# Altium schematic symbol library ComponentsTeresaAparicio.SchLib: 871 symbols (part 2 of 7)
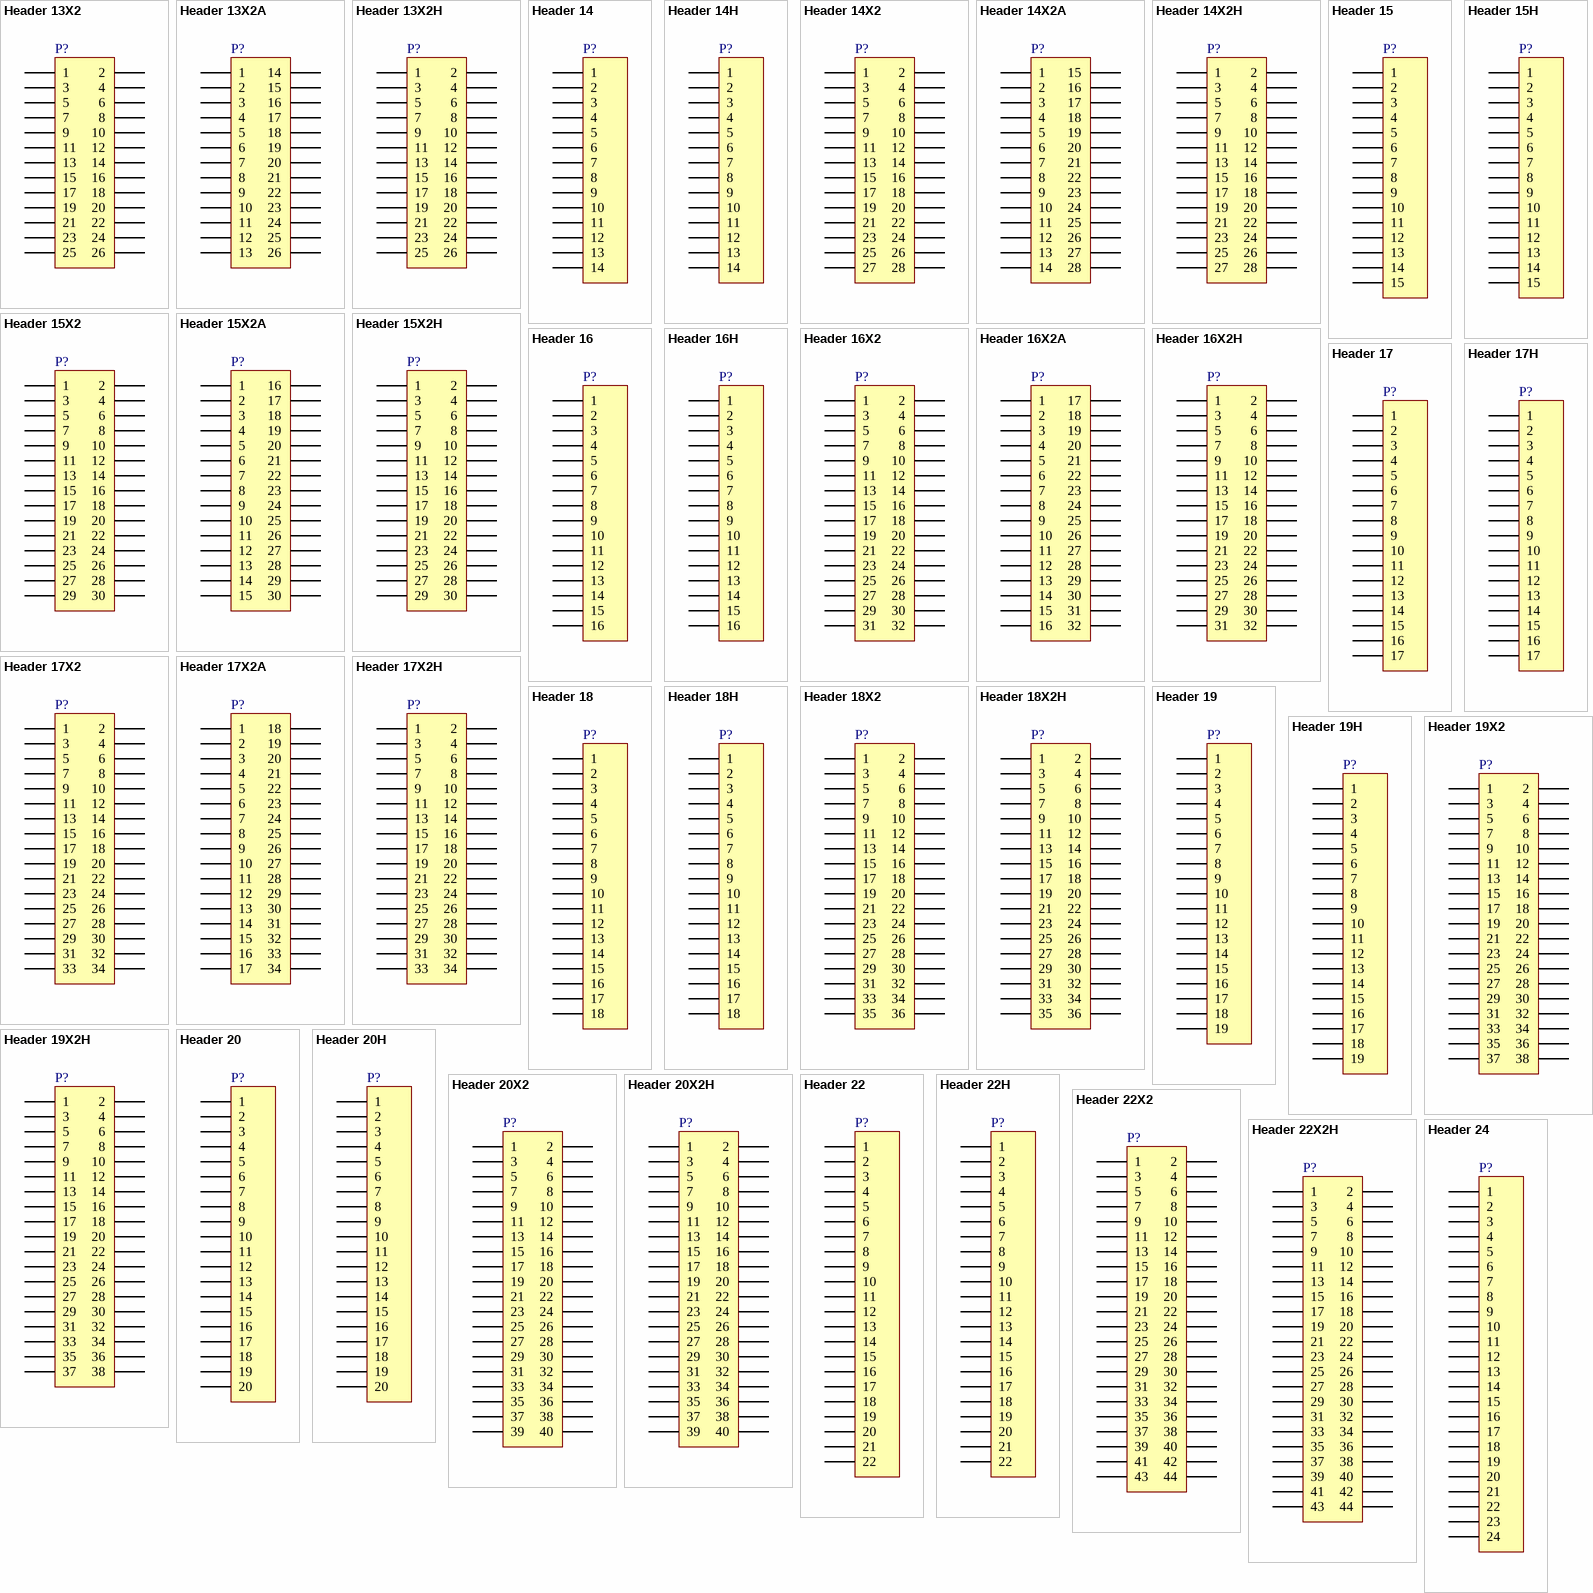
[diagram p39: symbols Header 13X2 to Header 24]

## Header 15X2A
designator P?
Header, 15-Pin, Dual row
footprint HDR2X15_CEN (Connector; Header; 15x2 Position)
signal-integrity model Connector
pins: 1, 2, 3, 4, 5, 6, 7, 8, 9, 10, 11, 12, 13, 14, 15, 16, 17, 18, 19, 20, 21, 22, 23, 24, 25, 26, 27, 28, 29, 30

## Header 15X2H
designator P?
Header, 15-Pin, Dual row, Right Angle
footprint HDR2X15H (Connector; Header; 15x2 Position; Right Angle)
signal-integrity model Connector
pins: 1, 2, 3, 4, 5, 6, 7, 8, 9, 10, 11, 12, 13, 14, 15, 16, 17, 18, 19, 20, 21, 22, 23, 24, 25, 26, 27, 28, 29, 30

## Header 16
designator P?
Header, 16-Pin
footprint HDR1X16 (Connector; Header; 16 Position)
signal-integrity model Connector
pins: 1, 2, 3, 4, 5, 6, 7, 8, 9, 10, 11, 12, 13, 14, 15, 16

## Header 16H
designator P?
Header, 16-Pin, Right Angle
footprint HDR1X16H (Connector; Header; 16 Position; Right Angle)
signal-integrity model Connector
pins: 1, 2, 3, 4, 5, 6, 7, 8, 9, 10, 11, 12, 13, 14, 15, 16

## Header 16X2
designator P?
Header, 16-Pin, Dual row
footprint HDR2X16 (Connector; Header; 16x2 Position)
signal-integrity model Connector
pins: 1, 2, 3, 4, 5, 6, 7, 8, 9, 10, 11, 12, 13, 14, 15, 16, 17, 18, 19, 20, 21, 22, 23, 24, 25, 26, 27, 28, 29, 30, 31, 32

## Header 16X2A
designator P?
Header, 16-Pin, Dual row
footprint HDR2X16_CEN (Connector; Header; 16x2 Position)
signal-integrity model Connector
pins: 1, 2, 3, 4, 5, 6, 7, 8, 9, 10, 11, 12, 13, 14, 15, 16, 17, 18, 19, 20, 21, 22, 23, 24, 25, 26, 27, 28, 29, 30, 31, 32

## Header 16X2H
designator P?
Header, 16-Pin, Dual row, Right Angle
footprint HDR2X16H (Connector; Header; 16x2 Position; Right Angle)
signal-integrity model Connector
pins: 1, 2, 3, 4, 5, 6, 7, 8, 9, 10, 11, 12, 13, 14, 15, 16, 17, 18, 19, 20, 21, 22, 23, 24, 25, 26, 27, 28, 29, 30, 31, 32

## Header 17
designator P?
Header, 17-Pin
footprint HDR1X17 (Connector; Header; 17 Position)
signal-integrity model Connector
pins: 1, 2, 3, 4, 5, 6, 7, 8, 9, 10, 11, 12, 13, 14, 15, 16, 17

## Header 17H
designator P?
Header, 17-Pin, Right Angle
footprint HDR1X17H (Connector; Header; 17 Position; Right Angle)
signal-integrity model Connector
pins: 1, 2, 3, 4, 5, 6, 7, 8, 9, 10, 11, 12, 13, 14, 15, 16, 17

## Header 17X2
designator P?
Header, 17-Pin, Dual row
footprint HDR2X17 (Connector; Header; 17x2 Position)
signal-integrity model Connector
pins: 1, 2, 3, 4, 5, 6, 7, 8, 9, 10, 11, 12, 13, 14, 15, 16, 17, 18, 19, 20, 21, 22, 23, 24, 25, 26, 27, 28, 29, 30, 31, 32, 33, 34

## Header 17X2A
designator P?
Header, 17-Pin, Dual row
footprint HDR2X17_CEN (Connector; Header; 17x2 Position)
signal-integrity model Connector
pins: 1, 2, 3, 4, 5, 6, 7, 8, 9, 10, 11, 12, 13, 14, 15, 16, 17, 18, 19, 20, 21, 22, 23, 24, 25, 26, 27, 28, 29, 30, 31, 32, 33, 34

## Header 17X2H
designator P?
Header, 17-Pin, Dual row, Right Angle
footprint HDR2X17H (Connector; Header; 17x2 Position; Right Angle)
signal-integrity model Connector
pins: 1, 2, 3, 4, 5, 6, 7, 8, 9, 10, 11, 12, 13, 14, 15, 16, 17, 18, 19, 20, 21, 22, 23, 24, 25, 26, 27, 28, 29, 30, 31, 32, 33, 34

## Header 18
designator P?
Header, 18-Pin
footprint HDR1X18 (Connector; Header; 18 Position)
signal-integrity model Connector
pins: 1, 2, 3, 4, 5, 6, 7, 8, 9, 10, 11, 12, 13, 14, 15, 16, 17, 18

## Header 18H
designator P?
Header, 18-Pin, Right Angle
footprint HDR1X18H (Connector; Header; 18 Position; Right Angle)
signal-integrity model Connector
pins: 1, 2, 3, 4, 5, 6, 7, 8, 9, 10, 11, 12, 13, 14, 15, 16, 17, 18

## Header 18X2
designator P?
Header, 18-Pin, Dual row
footprint HDR2X18 (Connector; Header; 18x2 Position)
signal-integrity model Connector
pins: 1, 2, 3, 4, 5, 6, 7, 8, 9, 10, 11, 12, 13, 14, 15, 16, 17, 18, 19, 20, 21, 22, 23, 24, 25, 26, 27, 28, 29, 30, 31, 32, 33, 34, 35, 36

## Header 18X2H
designator P?
Header, 18-Pin, Dual row, Right Angle
footprint HDR2X18H (Connector; Header; 18x2 Position; Right Angle)
signal-integrity model Connector
pins: 1, 2, 3, 4, 5, 6, 7, 8, 9, 10, 11, 12, 13, 14, 15, 16, 17, 18, 19, 20, 21, 22, 23, 24, 25, 26, 27, 28, 29, 30, 31, 32, 33, 34, 35, 36

## Header 19
designator P?
Header, 19-Pin
footprint HDR1X19 (Connector; Header; 19 Position)
signal-integrity model Connector
pins: 1, 2, 3, 4, 5, 6, 7, 8, 9, 10, 11, 12, 13, 14, 15, 16, 17, 18, 19

## Header 19H
designator P?
Header, 19-Pin, Right Angle
footprint HDR1X19H (Connector; Header; 19 Position; Right Angle)
signal-integrity model Connector
pins: 1, 2, 3, 4, 5, 6, 7, 8, 9, 10, 11, 12, 13, 14, 15, 16, 17, 18, 19

## Header 19X2
designator P?
Header, 19-Pin, Dual row
footprint HDR2X19 (Connector; Header; 19x2 Position)
signal-integrity model Connector
pins: 1, 2, 3, 4, 5, 6, 7, 8, 9, 10, 11, 12, 13, 14, 15, 16, 17, 18, 19, 20, 21, 22, 23, 24, 25, 26, 27, 28, 29, 30, 31, 32, 33, 34, 35, 36, 37, 38

## Header 19X2H
designator P?
Header, 19-Pin, Dual row, Right Angle
footprint HDR2X19H (Connector; Header; 19x2 Position; Right Angle)
signal-integrity model Connector
pins: 1, 2, 3, 4, 5, 6, 7, 8, 9, 10, 11, 12, 13, 14, 15, 16, 17, 18, 19, 20, 21, 22, 23, 24, 25, 26, 27, 28, 29, 30, 31, 32, 33, 34, 35, 36, 37, 38

## Header 20
designator P?
Header, 20-Pin
footprint HDR1X20 (Connector; Header; 20 Position)
signal-integrity model Connector
pins: 1, 2, 3, 4, 5, 6, 7, 8, 9, 10, 11, 12, 13, 14, 15, 16, 17, 18, 19, 20

## Header 20H
designator P?
Header, 20-Pin, Right Angle
footprint HDR1X20H (Connector; Header; 20 Position; Right Angle)
signal-integrity model Connector
pins: 1, 2, 3, 4, 5, 6, 7, 8, 9, 10, 11, 12, 13, 14, 15, 16, 17, 18, 19, 20

## Header 20X2
designator P?
Header, 20-Pin, Dual row
footprint HDR2X20 (Connector; Header; 20x2 Position)
signal-integrity model Connector
pins: 1, 2, 3, 4, 5, 6, 7, 8, 9, 10, 11, 12, 13, 14, 15, 16, 17, 18, 19, 20, 21, 22, 23, 24, 25, 26, 27, 28, 29, 30, 31, 32, 33, 34, 35, 36, 37, 38, 39, 40

## Header 20X2H
designator P?
Header, 20-Pin, Dual row, Right Angle
footprint HDR2X20H (Connector; Header; 20x2 Position; Right Angle)
signal-integrity model Connector
pins: 1, 2, 3, 4, 5, 6, 7, 8, 9, 10, 11, 12, 13, 14, 15, 16, 17, 18, 19, 20, 21, 22, 23, 24, 25, 26, 27, 28, 29, 30, 31, 32, 33, 34, 35, 36, 37, 38, 39, 40

## Header 22
designator P?
Header, 22-Pin
footprint HDR1X22 (Connector; Header; 22 Position)
signal-integrity model Connector
pins: 1, 2, 3, 4, 5, 6, 7, 8, 9, 10, 11, 12, 13, 14, 15, 16, 17, 18, 19, 20, 21, 22

## Header 22H
designator P?
Header, 22-Pin, Right Angle
footprint HDR1X22H (Connector; Header; 22 Position; Right Angle)
signal-integrity model Connector
pins: 1, 2, 3, 4, 5, 6, 7, 8, 9, 10, 11, 12, 13, 14, 15, 16, 17, 18, 19, 20, 21, 22

## Header 22X2
designator P?
Header, 22-Pin, Dual row
footprint HDR2X22 (Connector; Header; 22x2 Position)
signal-integrity model Connector
pins: 1, 2, 3, 4, 5, 6, 7, 8, 9, 10, 11, 12, 13, 14, 15, 16, 17, 18, 19, 20, 21, 22, 23, 24, 25, 26, 27, 28, 29, 30, 31, 32, 33, 34, 35, 36, 37, 38, 39, 40, 41, 42, 43, 44

## Header 22X2H
designator P?
Header, 22-Pin, Dual row, Right Angle
footprint HDR2X22H (Connector; Header; 22x2 Position; Right Angle)
signal-integrity model Connector
pins: 1, 2, 3, 4, 5, 6, 7, 8, 9, 10, 11, 12, 13, 14, 15, 16, 17, 18, 19, 20, 21, 22, 23, 24, 25, 26, 27, 28, 29, 30, 31, 32, 33, 34, 35, 36, 37, 38, 39, 40, 41, 42, 43, 44

## Header 24
designator P?
Header, 24-Pin
footprint HDR1X24 (Connector; Header; 24 Position)
signal-integrity model Connector
pins: 1, 2, 3, 4, 5, 6, 7, 8, 9, 10, 11, 12, 13, 14, 15, 16, 17, 18, 19, 20, 21, 22, 23, 24

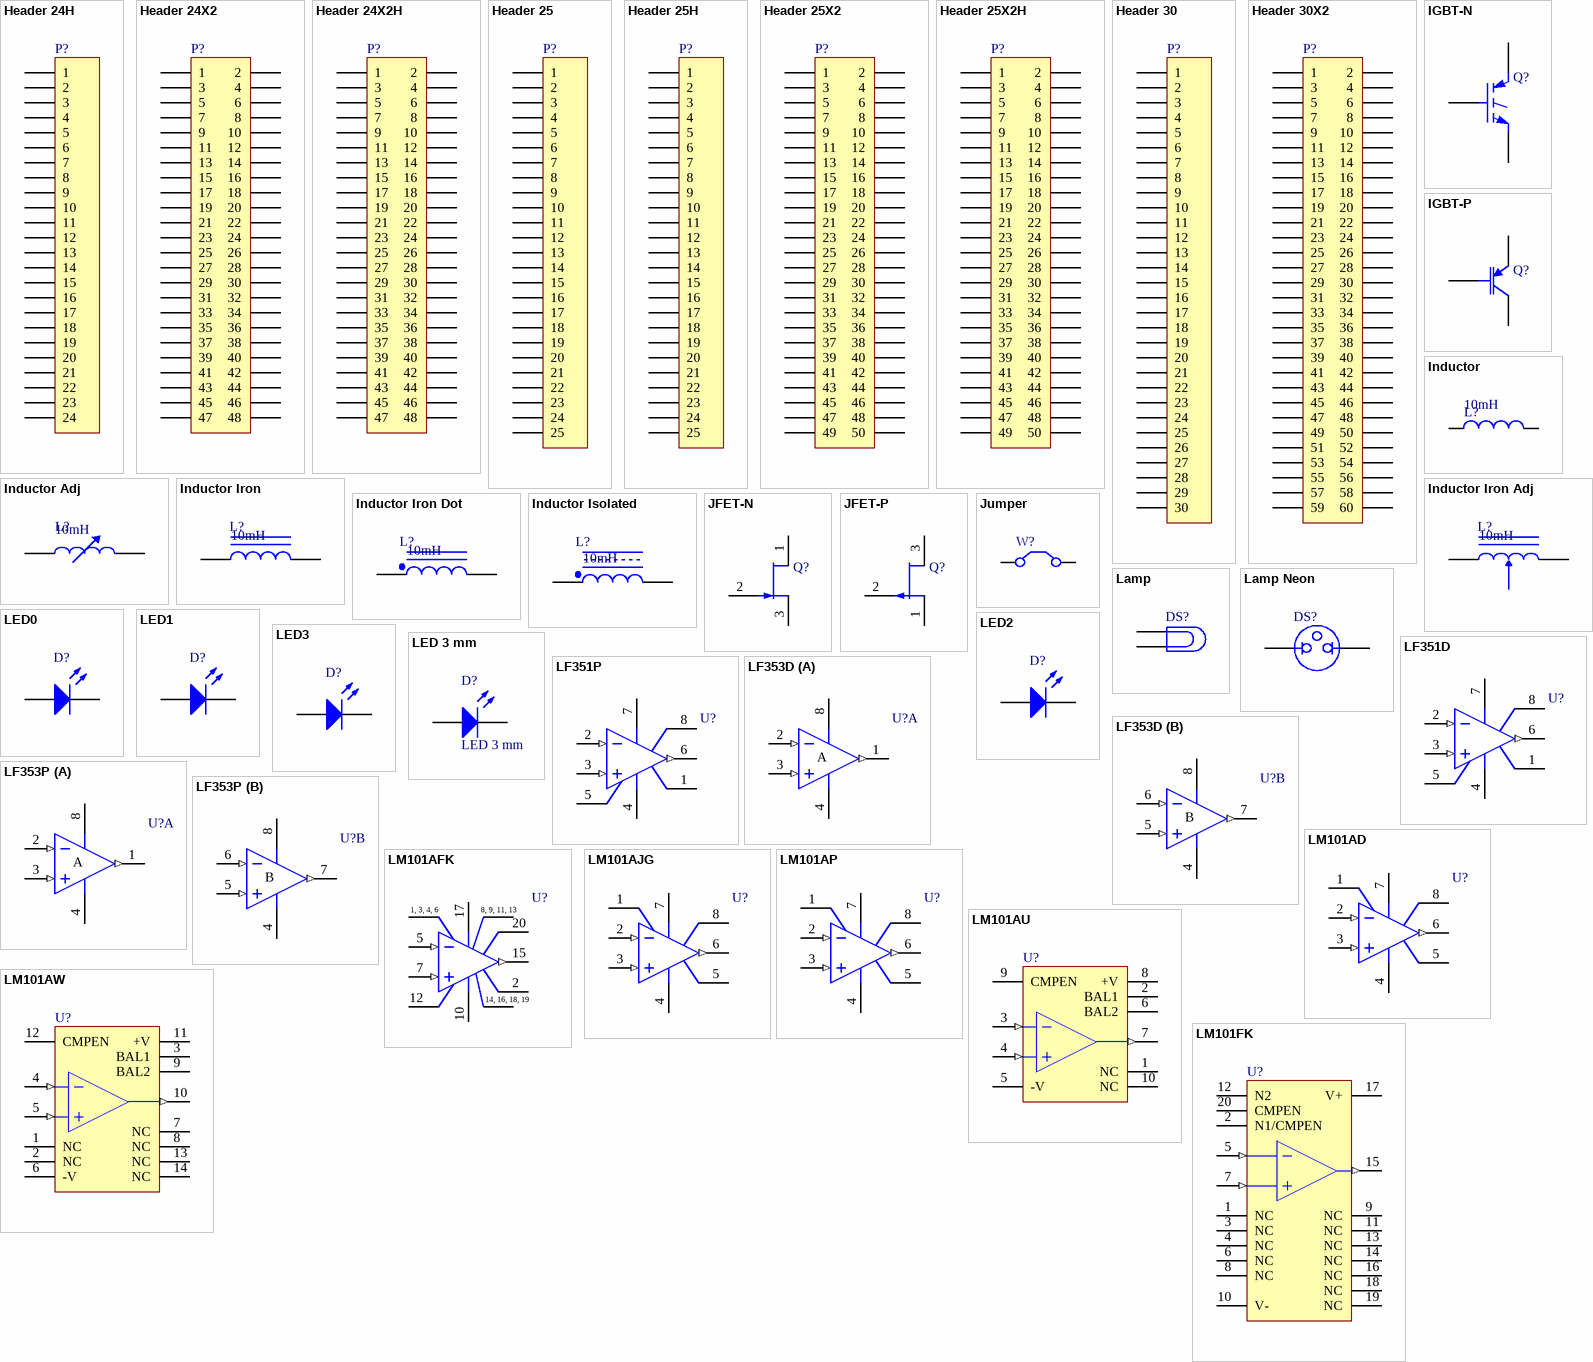
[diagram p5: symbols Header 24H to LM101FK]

## Header 24H
designator P?
Header, 24-Pin, Right Angle
footprint HDR1X24H (Connector; Header; 24 Position; Right Angle)
signal-integrity model Connector
pins: 1, 2, 3, 4, 5, 6, 7, 8, 9, 10, 11, 12, 13, 14, 15, 16, 17, 18, 19, 20, 21, 22, 23, 24

## Header 24X2
designator P?
Header, 24-Pin, Dual row
footprint HDR2X24 (Connector; Header; 24x2 Position)
signal-integrity model Connector
pins: 1, 2, 3, 4, 5, 6, 7, 8, 9, 10, 11, 12, 13, 14, 15, 16, 17, 18, 19, 20, 21, 22, 23, 24, 25, 26, 27, 28, 29, 30, 31, 32, 33, 34, 35, 36, 37, 38, 39, 40, 41, 42, 43, 44, 45, 46, 47, 48

## Header 24X2H
designator P?
Header, 24-Pin, Dual row, Right Angle
footprint HDR2X24H (Connector; Header; 24x2 Position; Right Angle)
signal-integrity model Connector
pins: 1, 2, 3, 4, 5, 6, 7, 8, 9, 10, 11, 12, 13, 14, 15, 16, 17, 18, 19, 20, 21, 22, 23, 24, 25, 26, 27, 28, 29, 30, 31, 32, 33, 34, 35, 36, 37, 38, 39, 40, 41, 42, 43, 44, 45, 46, 47, 48

## Header 25
designator P?
Header, 25-Pin
footprint HDR1X25 (Connector; Header; 25 Position)
signal-integrity model Connector
pins: 1, 2, 3, 4, 5, 6, 7, 8, 9, 10, 11, 12, 13, 14, 15, 16, 17, 18, 19, 20, 21, 22, 23, 24, 25

## Header 25H
designator P?
Header, 25-Pin, Right Angle
footprint HDR1X25H (Connector; Header; 25 Position; Right Angle)
signal-integrity model Connector
pins: 1, 2, 3, 4, 5, 6, 7, 8, 9, 10, 11, 12, 13, 14, 15, 16, 17, 18, 19, 20, 21, 22, 23, 24, 25

## Header 25X2
designator P?
Header, 25-Pin, Dual row
footprint HDR2X25 (Connector; Header; 25x2 Position)
signal-integrity model Connector
pins: 1, 2, 3, 4, 5, 6, 7, 8, 9, 10, 11, 12, 13, 14, 15, 16, 17, 18, 19, 20, 21, 22, 23, 24, 25, 26, 27, 28, 29, 30, 31, 32, 33, 34, 35, 36, 37, 38, 39, 40, 41, 42, 43, 44, 45, 46, 47, 48, 49, 50

## Header 25X2H
designator P?
Header, 25-Pin, Dual row, Right Angle
footprint HDR2X25H (Connector; Header; 25x2 Position; Right Angle)
signal-integrity model Connector
pins: 1, 2, 3, 4, 5, 6, 7, 8, 9, 10, 11, 12, 13, 14, 15, 16, 17, 18, 19, 20, 21, 22, 23, 24, 25, 26, 27, 28, 29, 30, 31, 32, 33, 34, 35, 36, 37, 38, 39, 40, 41, 42, 43, 44, 45, 46, 47, 48, 49, 50

## Header 30
designator P?
Header, 30-Pin
footprint HDR1X30 (Connector; Header; 30 Position)
signal-integrity model Connector
pins: 1, 2, 3, 4, 5, 6, 7, 8, 9, 10, 11, 12, 13, 14, 15, 16, 17, 18, 19, 20, 21, 22, 23, 24, 25, 26, 27, 28, 29, 30

## Header 30X2
designator P?
Header, 30-Pin, Dual row
footprint HDR2X30 (Connector; Header; 30x2 Position)
signal-integrity model Connector
pins: 1, 2, 3, 4, 5, 6, 7, 8, 9, 10, 11, 12, 13, 14, 15, 16, 17, 18, 19, 20, 21, 22, 23, 24, 25, 26, 27, 28, 29, 30, 31, 32, 33, 34, 35, 36, 37, 38, 39, 40, 41, 42, 43, 44, 45, 46, 47, 48, 49, 50, 51, 52, 53, 54, 55, 56, 57, 58, 59, 60

## IGBT-N
designator Q?
Insulated Gate Bipolar Transistor (N-Channel)
footprint TO-247 (SIP with Mounting Hole; 3 Leads; Body 20 x 15.6 x 5 mm (typ); Pitch 5.45 mm)
simulation model IRGPC40U (Spice Subcircuit)
pins: 1 G, 2 C, 3 E

## IGBT-P
designator Q?
PNP Bipolar Junction Transistor
footprint TO-264-AA (SIP with Mounting Hole; 3 Leads; Body 26 x 20 x 5 mm (typ); Pitch 5.45 mm)
simulation model PIGBT (Spice Subcircuit)
pins: 1 C, 2 G, 3 E

## Inductor
designator L?  value 10mH
Inductor; Code_IEC: 1005
footprint 0402-A (Chip Inductor, Body 1.0x0.5mm, IPC High Density)
footprint INDC1608L (Chip Inductor, Body 1.6x0.8mm, IPC High Density)
footprint 2029 (Chip Inductor, Body 2.0x1.2mm, IPC High Density)
footprint 0603 (Chip Inductor, Body 0.6x0.3mm, IPC High Density)
footprint INDC3216 (Chip Inductor, Body 3.2x1.6mm, IPC High Density)
footprint INDC4532 (Chip Inductor, Body 4.5x3.2mm, IPC High Density)
simulation model INDUCTOR (Inductor)
signal-integrity model Inductor
pins: 1, 2

## Inductor Adj
designator L?  value 10mH
Adjustable Inductor; Set Position: 0.5
footprint AXIAL-0.8 (Axial Device, Thru-Hole; 2 Leads; 0.8 in Pin Spacing)
simulation model INDUCTOR (Inductor)
signal-integrity model Inductor Adj
pins: 1, 2

## Inductor Iron
designator L?  value 10mH
Magnetic-Core Inductor
footprint AXIAL-0.9 (Axial Device, Thru-Hole; 2 Leads; 0.9 in Pin Spacing)
simulation model INDUCTOR (Inductor)
signal-integrity model Inductor Iron
pins: 1, 2

## Inductor Iron Adj
designator L?  value 10mH
Adjustable Magnetic-Core Inductor; Set Position: 0.5
footprint AXIAL-1.0 (Axial Device, Thru-Hole; 2 Leads; 1.0 in Pin Spacing)
simulation model INDUCTOR (Inductor)
signal-integrity model Inductor Iron Adj
pins: 1, 2

## Inductor Iron Dot
designator L?  value 10mH
Magnetic-Core Inductor with Winding Polarity Marking
footprint DIODE_SMC (Diode; 2 Leads)
signal-integrity model Inductor Iron Dot
pins: 1, 2

## Inductor Isolated
designator L?  value 10mH
Isolated Inductor
footprint 425 (SOD-123; 2 Leads; Body 2.7 x 1.6 mm, (LxW))
signal-integrity model Inductor Isolated
pins: 1, 2

## JFET-N
designator Q?
N-Channel JFET
footprint TO-254-AA (TO, Thru-Hole, Vertical, Heatsink Mounted; 3 In-Line Leads; Pitch 3.81 mm)
simulation model NJFET
pins: 1 D, 2 G, 3 S

## JFET-P
designator Q?
P-Channel JFET
footprint TO-18A (SC-89; 3 Flat Leads; Body 1.6 x 1.6 x 0.7 mm, inc leads (LxWxH typ))
simulation model PJFET
pins: 1 D, 2 G, 3 S

## Jumper
designator W?
Jumper Wire
footprint RAD-0.2 (Radial Cap, Thru-Hole; 2 Leads; 0.2 in Pin Spacing)
pins: 1 C1, 2 C2

## Lamp
designator DS?
Incandescent Bulb
footprint PIN2 (Incandescent Bulb; 2 Leads)
pins: 1, 2

## Lamp Neon
designator DS?
Neon Lamp
footprint PIN2 (Neon Lamp; 2 Leads)
pins: 1, 2

## LED0
designator D?
Typical INFRARED GaAs LED
footprint LED-0 (LED; 2 Leads)
simulation model LED0 (Diode)
pins: 1 A, 2 K

## LED1
designator D?
Typical RED GaAs LED
footprint LED-1 (LED; 2 Leads)
simulation model LED1 (Diode)
pins: 1 A, 2 K

## LED2
designator D?
Typical RED, GREEN, YELLOW, AMBER GaAs LED
footprint LED 3 mm (SMT LED; 2 Flat Leads)
simulation model LED2 (Diode)
3D model Model Name (PCB3D Model)
pins: 1 A, 2 K

## LED3
designator D?
Typical BLUE SiC LED
footprint 3.5X2.8X1.9 (SM LED; 2 C-Bend Leads; Body 3.5 x 2.8 x 1.9 mm, inc leads (LxWxH typ))
simulation model LED3 (Diode)
signal-integrity model LED
pins: 1 A, 2 K

## LED 3 mm
designator D?
Typical RED, GREEN, YELLOW, AMBER GaAs LED
simulation model LED2 (Diode)
3D model Model Name (PCB3D Model)
footprint LED-Polarized
pins: A 1, C 1

## LF351D
designator U?
Operational Amplifier; Note: Pin 8 is not connected; ComponentAvailability: Obsolete
footprint D008_L (SOIC, 8-Leads, Body 4.9x3.9mm, Pitch 1.27mm, IPC High Density)
footprint D008_M (SOIC, 8-Leads, Body 4.9x3.9mm, Pitch 1.27mm, IPC Low Density)
footprint D008_M (SOIC, 8-Leads, Body 4.9x3.9mm, Pitch 1.27mm, IPC Low Density)
3D model D008 (8-Pin Small Outline Integrated Circuit 1.27 mm Pitch)
simulation model LF351 (SUBCKT)
pins: 1 OS TRIM, 2 IN- (in), 3 IN+ (in), 4 V- (power), 5 OS TRIM, 6 OUT (out), 7 V+ (power), 8 NC

## LF351P
designator U?
Operational Amplifier; Note: Pin 8 is not connected; ComponentAvailability: Obsolete
footprint P008 (DIP; 8 Leads; Row Spacing 7.62 mm; Pitch 2.54 mm)
3D model P008 (DIP; 8 Leads; Row Spacing 7.62 mm; Pitch 2.54 mm)
simulation model LF351 (SUBCKT)
pins: 1 OS TRIM, 2 IN- (in), 3 IN+ (in), 4 V- (power), 5 OS TRIM, 6 OUT (out), 7 V+ (power), 8 NC

## LF353D
designator U?
Dual Operational Amplifier
footprint D008_L (SOIC, 8-Leads, Body 4.9x3.9mm, Pitch 1.27mm, IPC High Density)
footprint D008_M (SOIC, 8-Leads, Body 4.9x3.9mm, Pitch 1.27mm, IPC Low Density)
footprint D008_M (SOIC, 8-Leads, Body 4.9x3.9mm, Pitch 1.27mm, IPC Low Density)
3D model D008 (8-Pin Small Outline Integrated Circuit 1.27 mm Pitch)
simulation model LF353 (SUBCKT)
pins on every part: 4 V- (power), 8 V+ (power)
part A pins: 1 OUT (out), 2 IN- (in), 3 IN+ (in)
part B pins: 5 IN+ (in), 6 IN- (in), 7 OUT (out)

## LF353P
designator U?
Dual Operational Amplifier
footprint P008 (DIP; 8 Leads; Row Spacing 7.62 mm; Pitch 2.54 mm)
3D model P008 (DIP; 8 Leads; Row Spacing 7.62 mm; Pitch 2.54 mm)
simulation model LF353 (SUBCKT)
pins on every part: 4 V- (power), 8 V+ (power)
part A pins: 1 OUT (out), 2 IN- (in), 3 IN+ (in)
part B pins: 5 IN+ (in), 6 IN- (in), 7 OUT (out)

## LM101AD
designator U?
High Performance Operational Amplifier; ComponentAvailability: Obsolete
footprint D008_L (SOIC, 8-Leads, Body 4.9x3.9mm, Pitch 1.27mm, IPC High Density)
footprint D008_M (SOIC, 8-Leads, Body 4.9x3.9mm, Pitch 1.27mm, IPC Low Density)
footprint D008_M (SOIC, 8-Leads, Body 4.9x3.9mm, Pitch 1.27mm, IPC Low Density)
3D model D008 (8-Pin Small Outline Integrated Circuit 1.27 mm Pitch)
simulation model LM101A (SUBCKT)
pins: 1 BAL1/CMPEN, 2 IN- (in), 3 IN+ (in), 4 V- (power), 5 BAL2, 6 OUT (out), 7 V+ (power), 8 CMPEN

## LM101AFK
designator U?
High Performance Operational Amplifier; Note: Pins 1,3,4,6,8,9,11,13,14,16,18 and 19 are not connected; ComponentAvailability: Obsolete
footprint FK020 (Leadless Chip Carrier; 20 Terminals; Body 8.9 x 8.9 mm)
simulation model LM101A (SUBCKT)
pins: 1 NC, 2 N1/COMP, 3 NC, 4 NC, 5 IN- (in), 6 NC, 7 IN+ (in), 8 NC, 9 NC, 10 V- (power), 11 NC, 12 N2, 13 NC, 14 NC, 15 OUT (out), 16 NC, 17 V+ (power), 18 NC, 19 NC, 20 COMP

## LM101AJG
designator U?
High Performance Operational Amplifier; ComponentAvailability: Obsolete
footprint JG008 (DIP; 8 Leads; Row Spacing 7.62 mm; Pitch 2.54 mm)
3D model JG008 (DIP; 8 Leads; Row Spacing 7.62 mm; Pitch 2.54 mm)
simulation model LM101A (SUBCKT)
pins: 1 BAL1/CMPEN, 2 IN- (in), 3 IN+ (in), 4 V- (power), 5 BAL2, 6 OUT (out), 7 V+ (power), 8 CMPEN

## LM101AP
designator U?
High Performance Operational Amplifier; ComponentAvailability: Obsolete
footprint P008 (DIP; 8 Leads; Row Spacing 7.62 mm; Pitch 2.54 mm)
3D model P008 (DIP; 8 Leads; Row Spacing 7.62 mm; Pitch 2.54 mm)
simulation model LM101A (SUBCKT)
pins: 1 BAL1/CMPEN, 2 IN- (in), 3 IN+ (in), 4 V- (power), 5 BAL2, 6 OUT (out), 7 V+ (power), 8 CMPEN

## LM101AU
designator U?
High Performance Operational Amplifier; Note: Pins 1 and 10 are not connected; ComponentAvailability: Obsolete
footprint U010 (DFP; 10 Leads; Body 7.1 x 6.4 mm (LxW max); Pitch 1.27 mm)
3D model U010 (DFP; 10 Leads; Body 7.1 x 6.4 mm (LxW max); Pitch 1.27 mm)
simulation model LM101A (SUBCKT)
pins: 1 NC, 2 BAL1, 3 IN- (in), 4 IN+ (in), 5 -V (power), 6 BAL2, 7 OUT (out), 8 +V (power), 9 CMPEN, 10 NC

## LM101AW
designator U?
High Performance Operational Amplifier; Note: Pins 1,2,7,8,13 and 14 are not connected; ComponentAvailability: Obsolete
footprint W014 (DFP; 14 Leads; Body 9.9 x 6.6 mm (LxW max); Pitch 1.27 mm)
3D model W014 (DFP; 14 Leads; Body 9.9 x 6.6 mm (LxW max); Pitch 1.27 mm)
simulation model LM101A (SUBCKT)
pins: 1 NC, 2 NC, 3 BAL1, 4 IN- (in), 5 IN+ (in), 6 -V (power), 7 NC, 8 NC, 9 BAL2, 10 OUT (out), 11 +V (power), 12 CMPEN, 13 NC, 14 NC

## LM101FK
designator U?
High-Performance Operational Amplifier
footprint FN020_N (Leaded Chip Carrier, 20-Leads, Body 9x9mm, Pitch 1.27mm, IPC Medium Density)
footprint FN020_L (Leaded Chip Carrier, 20-Leads, Body 9x9mm, Pitch 1.27mm, IPC High Density)
footprint FN020_M (Leaded Chip Carrier, 20-Leads, Body 9x9mm, Pitch 1.27mm, IPC Low Density)
3D model LM101A-FN020 (20-Pin Leaded Chip Carrier 1.27 mm Pitch)
pins: 1 NC, 2 N1/CMPEN, 3 NC, 4 NC, 5 IN- (in), 6 NC, 7 IN+ (in), 8 NC, 9 NC, 10 V- (power), 11 NC, 12 N2, 13 NC, 14 NC, 15 OUT (out), 16 NC, 17 V+ (power), 18 NC, 19 NC, 20 CMPEN

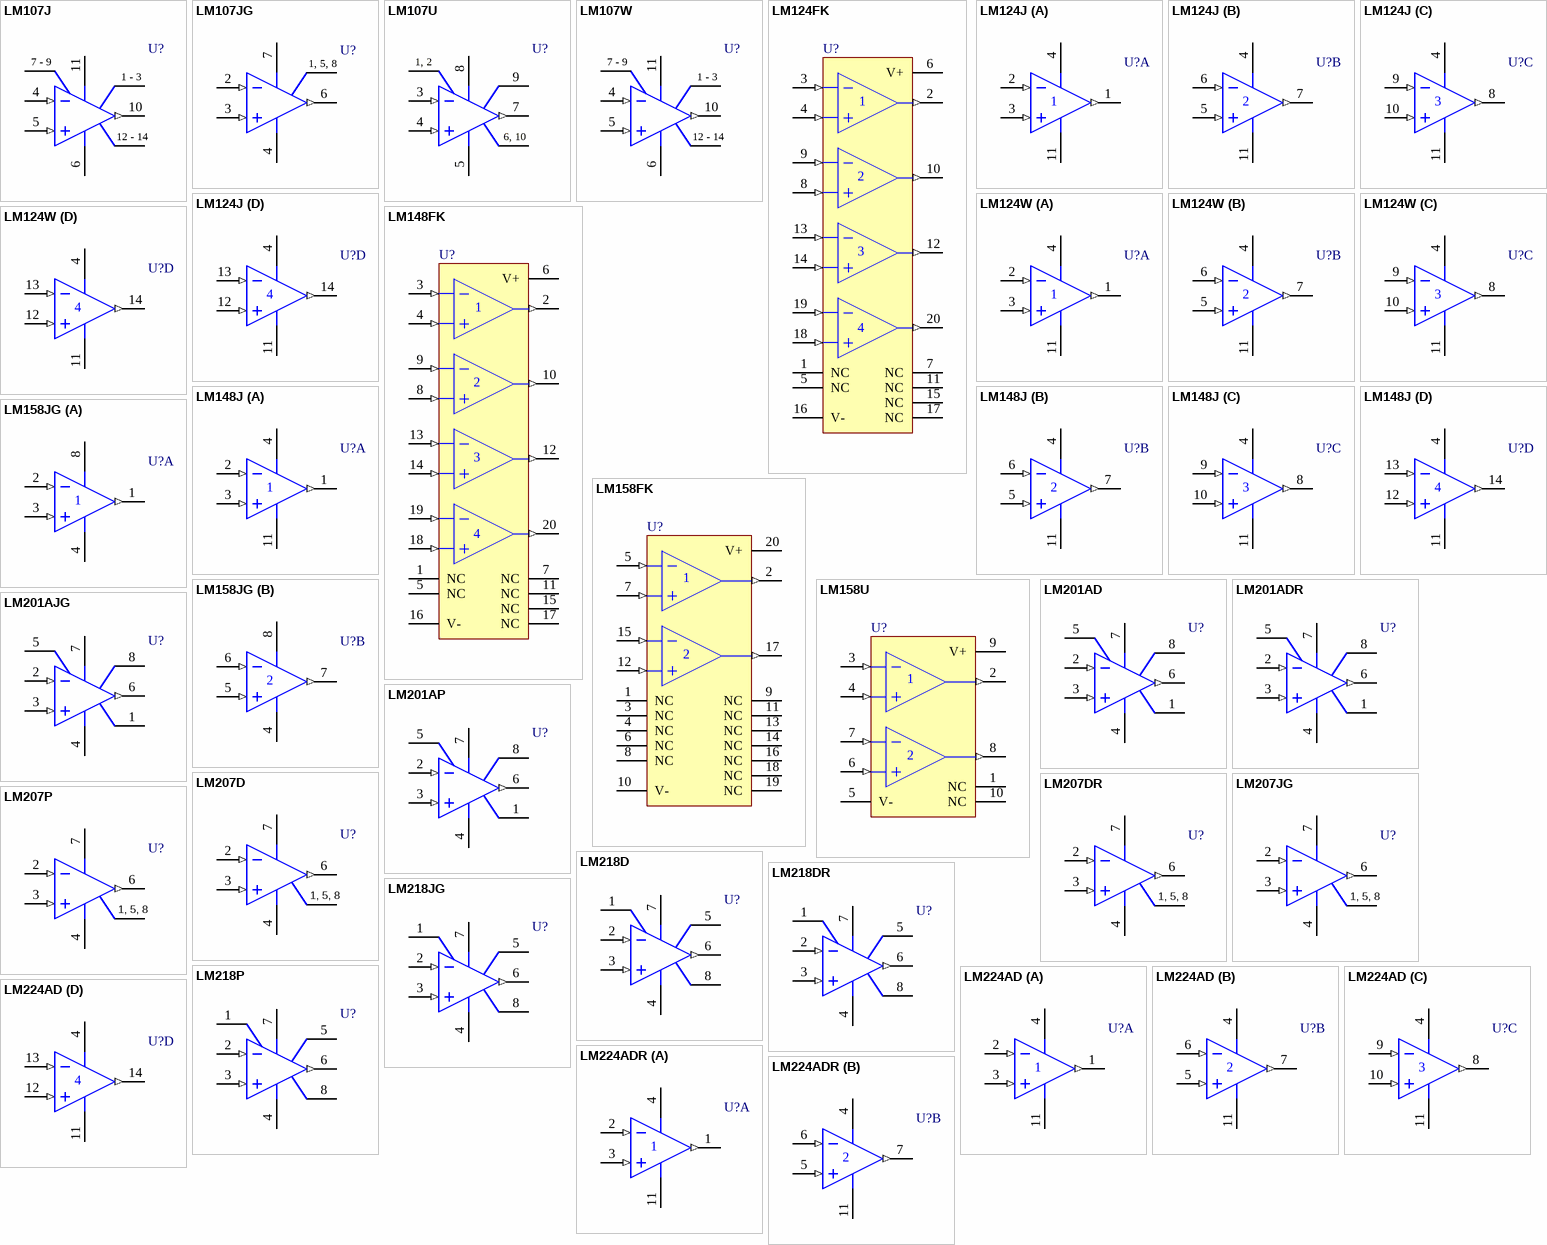
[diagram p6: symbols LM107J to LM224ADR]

## LM107J
designator U?
High Performance Operational Amplifier; Note: Pins 1,2,3,7,8,9,12,13 and 14 are not connected
footprint J014 (DIP; 14 Leads; Row Spacing 7.62 mm; Pitch 2.54 mm)
3D model J014 (DIP; 14 Leads; Row Spacing 7.62 mm; Pitch 2.54 mm)
simulation model LM107 (SUBCKT)
pins: 1 NC, 2 NC, 3 NC, 4 IN- (in), 5 IN+ (in), 6 V- (power), 7 NC, 8 NC, 9 NC, 10 OUT (out), 11 V+ (power), 12 NC, 13 NC, 14 NC

## LM107JG
designator U?
High Performance Operational Amplifier; Note: Pins 1,5 and 8 are not connected
footprint JG008 (DIP; 8 Leads; Row Spacing 7.62 mm; Pitch 2.54 mm)
3D model JG008 (DIP; 8 Leads; Row Spacing 7.62 mm; Pitch 2.54 mm)
simulation model LM107 (SUBCKT)
pins: 1 NC, 2 IN- (in), 3 IN+ (in), 4 V- (power), 5 NC, 6 OUT (out), 7 V+ (power), 8 NC

## LM107U
designator U?
High Performance Operational Amplifier
footprint U010 (DFP; 10 Leads; Body 7.1 x 6.4 mm (LxW max); Pitch 1.27 mm)
3D model U010 (DFP; 10 Leads; Body 7.1 x 6.4 mm (LxW max); Pitch 1.27 mm)
simulation model LM107 (SUBCKT)
pins: 1 NC, 2 NC, 3 IN- (in), 4 IN+ (in), 5 V-, 6 NC, 7 OUT (out), 8 V+ (power), 9 CMPEN, 10 NC

## LM107W
designator U?
High Performance Operational Amplifier; Note: Pins 1,2,3,7,8,9,12,13 and 14 are not connected
footprint W014 (DFP; 14 Leads; Body 9.9 x 6.6 mm (LxW max); Pitch 1.27 mm)
3D model W014 (DFP; 14 Leads; Body 9.9 x 6.6 mm (LxW max); Pitch 1.27 mm)
simulation model LM107 (SUBCKT)
pins: 1 NC, 2 NC, 3 NC, 4 IN- (in), 5 IN+ (in), 6 V- (power), 7 NC, 8 NC, 9 NC, 10 OUT (out), 11 V+ (power), 12 NC, 13 NC, 14 NC

## LM124FK
designator U?
Quadruple Operational Amplifier
footprint FK020 (Leadless Chip Carrier; 20 Terminals; Body 8.9 x 8.9 mm)
pins: 1 NC, 2 OUT (out), 3 IN- (in), 4 IN+ (in), 5 NC, 6 V+ (power), 7 NC, 8 IN+ (in), 9 IN- (in), 10 OUT (out), 11 NC, 12 OUT (out), 13 IN- (in), 14 IN+ (in), 15 NC, 16 V- (power), 17 NC, 18 IN+ (in), 19 IN- (in), 20 OUT (out)

## LM124J
designator U?
Quadruple Operational Amplifier
footprint J014 (DIP; 14 Leads; Row Spacing 7.62 mm; Pitch 2.54 mm)
3D model J014 (DIP; 14 Leads; Row Spacing 7.62 mm; Pitch 2.54 mm)
pins on every part: 4 V+ (power), 11 V- (power)
part A pins: 1 OUT (out), 2 IN- (in), 3 IN+ (in)
part B pins: 5 IN+ (in), 6 IN- (in), 7 OUT (out)
part C pins: 8 OUT (out), 9 IN- (in), 10 IN+ (in)
part D pins: 12 IN+ (in), 13 IN- (in), 14 OUT (out)

## LM124W
designator U?
Quadruple Operational Amplifier
footprint W014 (DFP; 14 Leads; Body 9.9 x 6.6 mm (LxW max); Pitch 1.27 mm)
3D model W014 (DFP; 14 Leads; Body 9.9 x 6.6 mm (LxW max); Pitch 1.27 mm)
pins on every part: 4 V+ (power), 11 V- (power)
part A pins: 1 OUT (out), 2 IN- (in), 3 IN+ (in)
part B pins: 5 IN+ (in), 6 IN- (in), 7 OUT (out)
part C pins: 8 OUT (out), 9 IN- (in), 10 IN+ (in)
part D pins: 12 IN+ (in), 13 IN- (in), 14 OUT (out)

## LM148FK
designator U?
Quadruple Operational Amplifier
footprint FK020 (Leadless Chip Carrier; 20 Terminals; Body 8.9 x 8.9 mm)
pins: 1 NC, 2 OUT (out), 3 IN- (in), 4 IN+ (in), 5 NC, 6 V+ (power), 7 NC, 8 IN+ (in), 9 IN- (in), 10 OUT (out), 11 NC, 12 OUT (out), 13 IN- (in), 14 IN+ (in), 15 NC, 16 V- (power), 17 NC, 18 IN+ (in), 19 IN- (in), 20 OUT (out)

## LM148J
designator U?
Quadruple Operational Amplifier
footprint J014 (DIP; 14 Leads; Row Spacing 7.62 mm; Pitch 2.54 mm)
3D model J014 (DIP; 14 Leads; Row Spacing 7.62 mm; Pitch 2.54 mm)
pins on every part: 4 V+ (power), 11 V- (power)
part A pins: 1 OUT (out), 2 IN- (in), 3 IN+ (in)
part B pins: 5 IN+ (in), 6 IN- (in), 7 OUT (out)
part C pins: 8 OUT (out), 9 IN- (in), 10 IN+ (in)
part D pins: 12 IN+ (in), 13 IN- (in), 14 OUT (out)

## LM158FK
designator U?
Dual Operational Amplifier
footprint FK020 (Leadless Chip Carrier; 20 Terminals; Body 8.9 x 8.9 mm)
pins: 1 NC, 2 OUT (out), 3 NC, 4 NC, 5 IN- (in), 6 NC, 7 IN+ (in), 8 NC, 9 NC, 10 V- (power), 11 NC, 12 IN+ (in), 13 NC, 14 NC, 15 IN- (in), 16 NC, 17 OUT (out), 18 NC, 19 NC, 20 V+ (power)

## LM158JG
designator U?
Dual Operational Amplifier
footprint JG008 (DIP; 8 Leads; Row Spacing 7.62 mm; Pitch 2.54 mm)
3D model JG008 (DIP; 8 Leads; Row Spacing 7.62 mm; Pitch 2.54 mm)
pins on every part: 4 V- (power), 8 V+ (power)
part A pins: 1 OUT (out), 2 IN- (in), 3 IN+ (in)
part B pins: 5 IN+ (in), 6 IN- (in), 7 OUT (out)

## LM158U
designator U?
Dual Operational Amplifier
footprint U010 (DFP; 10 Leads; Body 7.1 x 6.4 mm (LxW max); Pitch 1.27 mm)
3D model U010 (DFP; 10 Leads; Body 7.1 x 6.4 mm (LxW max); Pitch 1.27 mm)
pins: 1 NC, 2 OUT (out), 3 IN- (in), 4 IN+ (in), 5 V- (power), 6 IN+ (in), 7 IN- (in), 8 OUT (out), 9 V+ (power), 10 NC

## LM201AD
designator U?
High-Performance Operational Amplifier
footprint D008_L (SOIC, 8-Leads, Body 4.9x3.9mm, Pitch 1.27mm, IPC High Density)
footprint D008_M (SOIC, 8-Leads, Body 4.9x3.9mm, Pitch 1.27mm, IPC Low Density)
footprint D008_M (SOIC, 8-Leads, Body 4.9x3.9mm, Pitch 1.27mm, IPC Low Density)
3D model D008 (8-Pin Small Outline Integrated Circuit 1.27 mm Pitch)
pins: 1 N1/CMPEN, 2 IN- (in), 3 IN+ (in), 4 V- (power), 5 OS N2, 6 OUT (out), 7 V+ (power), 8 CMPEN

## LM201ADR
designator U?
High-Performance Operational Amplifier
footprint D008_L (SOIC, 8-Leads, Body 4.9x3.9mm, Pitch 1.27mm, IPC High Density)
footprint D008_M (SOIC, 8-Leads, Body 4.9x3.9mm, Pitch 1.27mm, IPC Low Density)
footprint D008_M (SOIC, 8-Leads, Body 4.9x3.9mm, Pitch 1.27mm, IPC Low Density)
3D model D008 (8-Pin Small Outline Integrated Circuit 1.27 mm Pitch)
pins: 1 N1/CMPEN, 2 IN- (in), 3 IN+ (in), 4 V- (power), 5 OS N2, 6 OUT (out), 7 V+ (power), 8 CMPEN

## LM201AJG
designator U?
High-Performance Operational Amplifier
footprint JG008 (DIP; 8 Leads; Row Spacing 7.62 mm; Pitch 2.54 mm)
3D model JG008 (DIP; 8 Leads; Row Spacing 7.62 mm; Pitch 2.54 mm)
pins: 1 N1/CMPEN, 2 IN- (in), 3 IN+ (in), 4 V- (power), 5 OS N2, 6 OUT (out), 7 V+ (power), 8 CMPEN

## LM201AP
designator U?
High-Performance Operational Amplifier; ComponentAvailability: Obsolete
footprint P008 (DIP; 8 Leads; Row Spacing 7.62 mm; Pitch 2.54 mm)
3D model P008 (DIP; 8 Leads; Row Spacing 7.62 mm; Pitch 2.54 mm)
pins: 1 N1/CMPEN, 2 IN- (in), 3 IN+ (in), 4 V- (power), 5 OS N2, 6 OUT (out), 7 V+ (power), 8 CMPEN

## LM207D
designator U?
High-Performance Operational Amplifier
footprint D008_L (SOIC, 8-Leads, Body 4.9x3.9mm, Pitch 1.27mm, IPC High Density)
footprint D008_M (SOIC, 8-Leads, Body 4.9x3.9mm, Pitch 1.27mm, IPC Low Density)
footprint D008_M (SOIC, 8-Leads, Body 4.9x3.9mm, Pitch 1.27mm, IPC Low Density)
3D model D008 (8-Pin Small Outline Integrated Circuit 1.27 mm Pitch)
pins: 1 NC, 2 IN- (in), 3 IN+ (in), 4 V- (power), 5 NC, 6 OUT (out), 7 V+ (power), 8 NC

## LM207DR
designator U?
High-Performance Operational Amplifier
footprint D008_L (SOIC, 8-Leads, Body 4.9x3.9mm, Pitch 1.27mm, IPC High Density)
footprint D008_M (SOIC, 8-Leads, Body 4.9x3.9mm, Pitch 1.27mm, IPC Low Density)
footprint D008_M (SOIC, 8-Leads, Body 4.9x3.9mm, Pitch 1.27mm, IPC Low Density)
3D model D008 (8-Pin Small Outline Integrated Circuit 1.27 mm Pitch)
pins: 1 NC, 2 IN- (in), 3 IN+ (in), 4 V- (power), 5 NC, 6 OUT (out), 7 V+ (power), 8 NC

## LM207JG
designator U?
High-Performance Operational Amplifier
footprint JG008 (DIP; 8 Leads; Row Spacing 7.62 mm; Pitch 2.54 mm)
3D model JG008 (DIP; 8 Leads; Row Spacing 7.62 mm; Pitch 2.54 mm)
pins: 1 NC, 2 IN- (in), 3 IN+ (in), 4 V- (power), 5 NC, 6 OUT (out), 7 V+ (power), 8 NC

## LM207P
designator U?
High-Performance Operational Amplifier
footprint P008 (DIP; 8 Leads; Row Spacing 7.62 mm; Pitch 2.54 mm)
3D model P008 (DIP; 8 Leads; Row Spacing 7.62 mm; Pitch 2.54 mm)
pins: 1 NC, 2 IN- (in), 3 IN+ (in), 4 V- (power), 5 NC, 6 OUT (out), 7 V+ (power), 8 NC

## LM218D
designator U?
High-Performance Operational Amplifier; ComponentAvailability: Obsolete
footprint D008_L (SOIC, 8-Leads, Body 4.9x3.9mm, Pitch 1.27mm, IPC High Density)
footprint D008_M (SOIC, 8-Leads, Body 4.9x3.9mm, Pitch 1.27mm, IPC Low Density)
footprint D008_M (SOIC, 8-Leads, Body 4.9x3.9mm, Pitch 1.27mm, IPC Low Density)
3D model D008 (8-Pin Small Outline Integrated Circuit 1.27 mm Pitch)
pins: 1 BAL/COMP, 2 IN- (in), 3 IN+ (in), 4 V- (power), 5 BAL/COMP3, 6 OUT (out), 7 V+ (power), 8 COMP2

## LM218DR
designator U?
High-Performance Operational Amplifier; ComponentAvailability: Obsolete
footprint D008_L (SOIC, 8-Leads, Body 4.9x3.9mm, Pitch 1.27mm, IPC High Density)
footprint D008_M (SOIC, 8-Leads, Body 4.9x3.9mm, Pitch 1.27mm, IPC Low Density)
footprint D008_M (SOIC, 8-Leads, Body 4.9x3.9mm, Pitch 1.27mm, IPC Low Density)
3D model D008 (8-Pin Small Outline Integrated Circuit 1.27 mm Pitch)
pins: 1 BAL/COMP, 2 IN- (in), 3 IN+ (in), 4 V- (power), 5 BAL/COMP3, 6 OUT (out), 7 V+ (power), 8 COMP2

## LM218JG
designator U?
High-Performance Operational Amplifier
footprint JG008 (DIP; 8 Leads; Row Spacing 7.62 mm; Pitch 2.54 mm)
3D model JG008 (DIP; 8 Leads; Row Spacing 7.62 mm; Pitch 2.54 mm)
pins: 1 BAL/COMP, 2 IN- (in), 3 IN+ (in), 4 V- (power), 5 BAL/COMP3, 6 OUT (out), 7 V+ (power), 8 COMP2

## LM218P
designator U?
High-Performance Operational Amplifier; ComponentAvailability: Obsolete
footprint P008 (DIP; 8 Leads; Row Spacing 7.62 mm; Pitch 2.54 mm)
3D model P008 (DIP; 8 Leads; Row Spacing 7.62 mm; Pitch 2.54 mm)
pins: 1 BAL/COMP, 2 IN- (in), 3 IN+ (in), 4 V- (power), 5 BAL/COMP3, 6 OUT (out), 7 V+ (power), 8 COMP2

## LM224AD
designator U?
Quadruple Operational Amplifier
footprint D014_N (SOIC, 14-Leads, Body 8.7x3.9mm, Pitch 1.27mm, IPC Medium Density)
footprint D014_L (SOIC, 14-Leads, Body 8.7x3.9mm, Pitch 1.27mm, IPC High Density)
footprint D014_M (SOIC, 14-Leads, Body 8.7x3.9mm, Pitch 1.27mm, IPC Low Density)
3D model D014 (14-Pin Small Outline Integrated Circuit 1.27 mm Pitch)
pins on every part: 4 V+ (power), 11 V- (power)
part A pins: 1 OUT (out), 2 IN- (in), 3 IN+ (in)
part B pins: 5 IN+ (in), 6 IN- (in), 7 OUT (out)
part C pins: 8 OUT (out), 9 IN- (in), 10 IN+ (in)
part D pins: 12 IN+ (in), 13 IN- (in), 14 OUT (out)

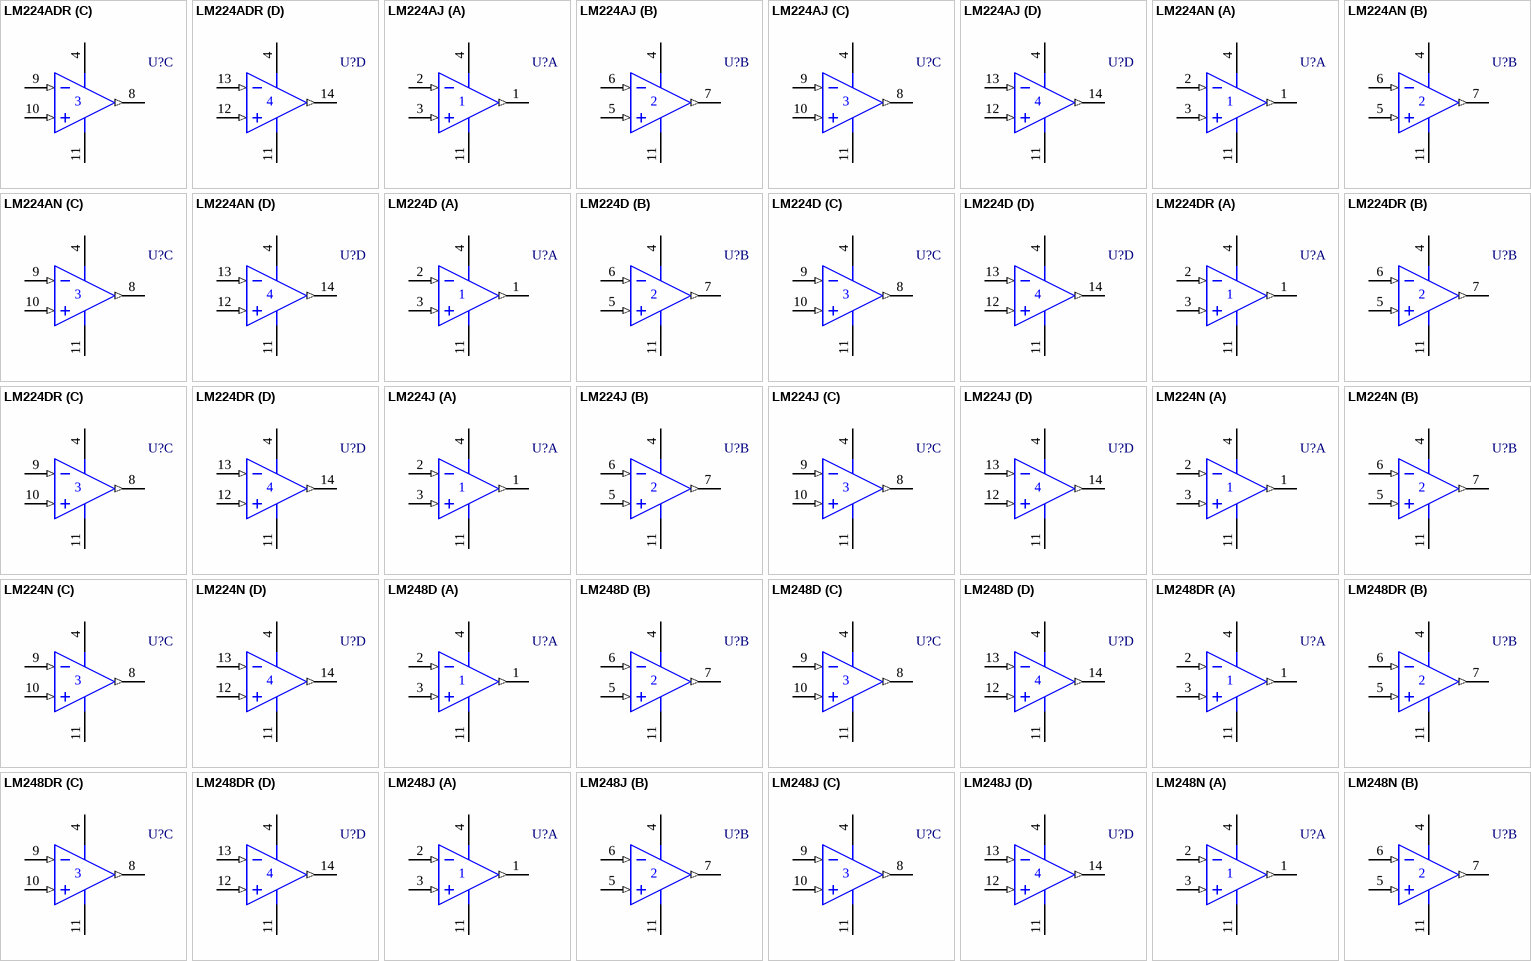
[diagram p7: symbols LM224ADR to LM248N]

## LM224ADR
designator U?
Quadruple Operational Amplifier
footprint D014_N (SOIC, 14-Leads, Body 8.7x3.9mm, Pitch 1.27mm, IPC Medium Density)
footprint D014_L (SOIC, 14-Leads, Body 8.7x3.9mm, Pitch 1.27mm, IPC High Density)
footprint D014_M (SOIC, 14-Leads, Body 8.7x3.9mm, Pitch 1.27mm, IPC Low Density)
3D model D014 (14-Pin Small Outline Integrated Circuit 1.27 mm Pitch)
pins on every part: 4 V+ (power), 11 V- (power)
part A pins: 1 OUT (out), 2 IN- (in), 3 IN+ (in)
part B pins: 5 IN+ (in), 6 IN- (in), 7 OUT (out)
part C pins: 8 OUT (out), 9 IN- (in), 10 IN+ (in)
part D pins: 12 IN+ (in), 13 IN- (in), 14 OUT (out)

## LM224AJ
designator U?
Quadruple Operational Amplifier
footprint J014 (DIP; 14 Leads; Row Spacing 7.62 mm; Pitch 2.54 mm)
3D model J014 (DIP; 14 Leads; Row Spacing 7.62 mm; Pitch 2.54 mm)
pins on every part: 4 V+ (power), 11 V- (power)
part A pins: 1 OUT (out), 2 IN- (in), 3 IN+ (in)
part B pins: 5 IN+ (in), 6 IN- (in), 7 OUT (out)
part C pins: 8 OUT (out), 9 IN- (in), 10 IN+ (in)
part D pins: 12 IN+ (in), 13 IN- (in), 14 OUT (out)

## LM224AN
designator U?
Quadruple Operational Amplifier
footprint N014 (DIP; 14 Leads; Row Spacing 7.62 mm; Pitch 2.54 mm)
3D model N014 (DIP; 14 Leads; Row Spacing 7.62 mm; Pitch 2.54 mm)
pins on every part: 4 V+ (power), 11 V- (power)
part A pins: 1 OUT (out), 2 IN- (in), 3 IN+ (in)
part B pins: 5 IN+ (in), 6 IN- (in), 7 OUT (out)
part C pins: 8 OUT (out), 9 IN- (in), 10 IN+ (in)
part D pins: 12 IN+ (in), 13 IN- (in), 14 OUT (out)

## LM224D
designator U?
Quadruple Operational Amplifier
footprint D014_N (SOIC, 14-Leads, Body 8.7x3.9mm, Pitch 1.27mm, IPC Medium Density)
footprint D014_L (SOIC, 14-Leads, Body 8.7x3.9mm, Pitch 1.27mm, IPC High Density)
footprint D014_M (SOIC, 14-Leads, Body 8.7x3.9mm, Pitch 1.27mm, IPC Low Density)
3D model D014 (14-Pin Small Outline Integrated Circuit 1.27 mm Pitch)
pins on every part: 4 V+ (power), 11 V- (power)
part A pins: 1 OUT (out), 2 IN- (in), 3 IN+ (in)
part B pins: 5 IN+ (in), 6 IN- (in), 7 OUT (out)
part C pins: 8 OUT (out), 9 IN- (in), 10 IN+ (in)
part D pins: 12 IN+ (in), 13 IN- (in), 14 OUT (out)

## LM224DR
designator U?
Quadruple Operational Amplifier
footprint D014_N (SOIC, 14-Leads, Body 8.7x3.9mm, Pitch 1.27mm, IPC Medium Density)
footprint D014_L (SOIC, 14-Leads, Body 8.7x3.9mm, Pitch 1.27mm, IPC High Density)
footprint D014_M (SOIC, 14-Leads, Body 8.7x3.9mm, Pitch 1.27mm, IPC Low Density)
3D model D014 (14-Pin Small Outline Integrated Circuit 1.27 mm Pitch)
pins on every part: 4 V+ (power), 11 V- (power)
part A pins: 1 OUT (out), 2 IN- (in), 3 IN+ (in)
part B pins: 5 IN+ (in), 6 IN- (in), 7 OUT (out)
part C pins: 8 OUT (out), 9 IN- (in), 10 IN+ (in)
part D pins: 12 IN+ (in), 13 IN- (in), 14 OUT (out)

## LM224J
designator U?
Quadruple Operational Amplifier
footprint J014 (DIP; 14 Leads; Row Spacing 7.62 mm; Pitch 2.54 mm)
3D model J014 (DIP; 14 Leads; Row Spacing 7.62 mm; Pitch 2.54 mm)
pins on every part: 4 V+ (power), 11 V- (power)
part A pins: 1 OUT (out), 2 IN- (in), 3 IN+ (in)
part B pins: 5 IN+ (in), 6 IN- (in), 7 OUT (out)
part C pins: 8 OUT (out), 9 IN- (in), 10 IN+ (in)
part D pins: 12 IN+ (in), 13 IN- (in), 14 OUT (out)

## LM224N
designator U?
Quadruple Operational Amplifier
footprint N014 (DIP; 14 Leads; Row Spacing 7.62 mm; Pitch 2.54 mm)
3D model N014 (DIP; 14 Leads; Row Spacing 7.62 mm; Pitch 2.54 mm)
pins on every part: 4 V+ (power), 11 V- (power)
part A pins: 1 OUT (out), 2 IN- (in), 3 IN+ (in)
part B pins: 5 IN+ (in), 6 IN- (in), 7 OUT (out)
part C pins: 8 OUT (out), 9 IN- (in), 10 IN+ (in)
part D pins: 12 IN+ (in), 13 IN- (in), 14 OUT (out)

## LM248D
designator U?
Quadruple Operational Amplifier
footprint D014_N (SOIC, 14-Leads, Body 8.7x3.9mm, Pitch 1.27mm, IPC Medium Density)
footprint D014_L (SOIC, 14-Leads, Body 8.7x3.9mm, Pitch 1.27mm, IPC High Density)
footprint D014_M (SOIC, 14-Leads, Body 8.7x3.9mm, Pitch 1.27mm, IPC Low Density)
3D model D014 (14-Pin Small Outline Integrated Circuit 1.27 mm Pitch)
pins on every part: 4 V+ (power), 11 V- (power)
part A pins: 1 OUT (out), 2 IN- (in), 3 IN+ (in)
part B pins: 5 IN+ (in), 6 IN- (in), 7 OUT (out)
part C pins: 8 OUT (out), 9 IN- (in), 10 IN+ (in)
part D pins: 12 IN+ (in), 13 IN- (in), 14 OUT (out)

## LM248DR
designator U?
Quadruple Operational Amplifier
footprint D014_N (SOIC, 14-Leads, Body 8.7x3.9mm, Pitch 1.27mm, IPC Medium Density)
footprint D014_L (SOIC, 14-Leads, Body 8.7x3.9mm, Pitch 1.27mm, IPC High Density)
footprint D014_M (SOIC, 14-Leads, Body 8.7x3.9mm, Pitch 1.27mm, IPC Low Density)
3D model D014 (14-Pin Small Outline Integrated Circuit 1.27 mm Pitch)
pins on every part: 4 V+ (power), 11 V- (power)
part A pins: 1 OUT (out), 2 IN- (in), 3 IN+ (in)
part B pins: 5 IN+ (in), 6 IN- (in), 7 OUT (out)
part C pins: 8 OUT (out), 9 IN- (in), 10 IN+ (in)
part D pins: 12 IN+ (in), 13 IN- (in), 14 OUT (out)

## LM248J
designator U?
Quadruple Operational Amplifier
footprint J014 (DIP; 14 Leads; Row Spacing 7.62 mm; Pitch 2.54 mm)
3D model J014 (DIP; 14 Leads; Row Spacing 7.62 mm; Pitch 2.54 mm)
pins on every part: 4 V+ (power), 11 V- (power)
part A pins: 1 OUT (out), 2 IN- (in), 3 IN+ (in)
part B pins: 5 IN+ (in), 6 IN- (in), 7 OUT (out)
part C pins: 8 OUT (out), 9 IN- (in), 10 IN+ (in)
part D pins: 12 IN+ (in), 13 IN- (in), 14 OUT (out)

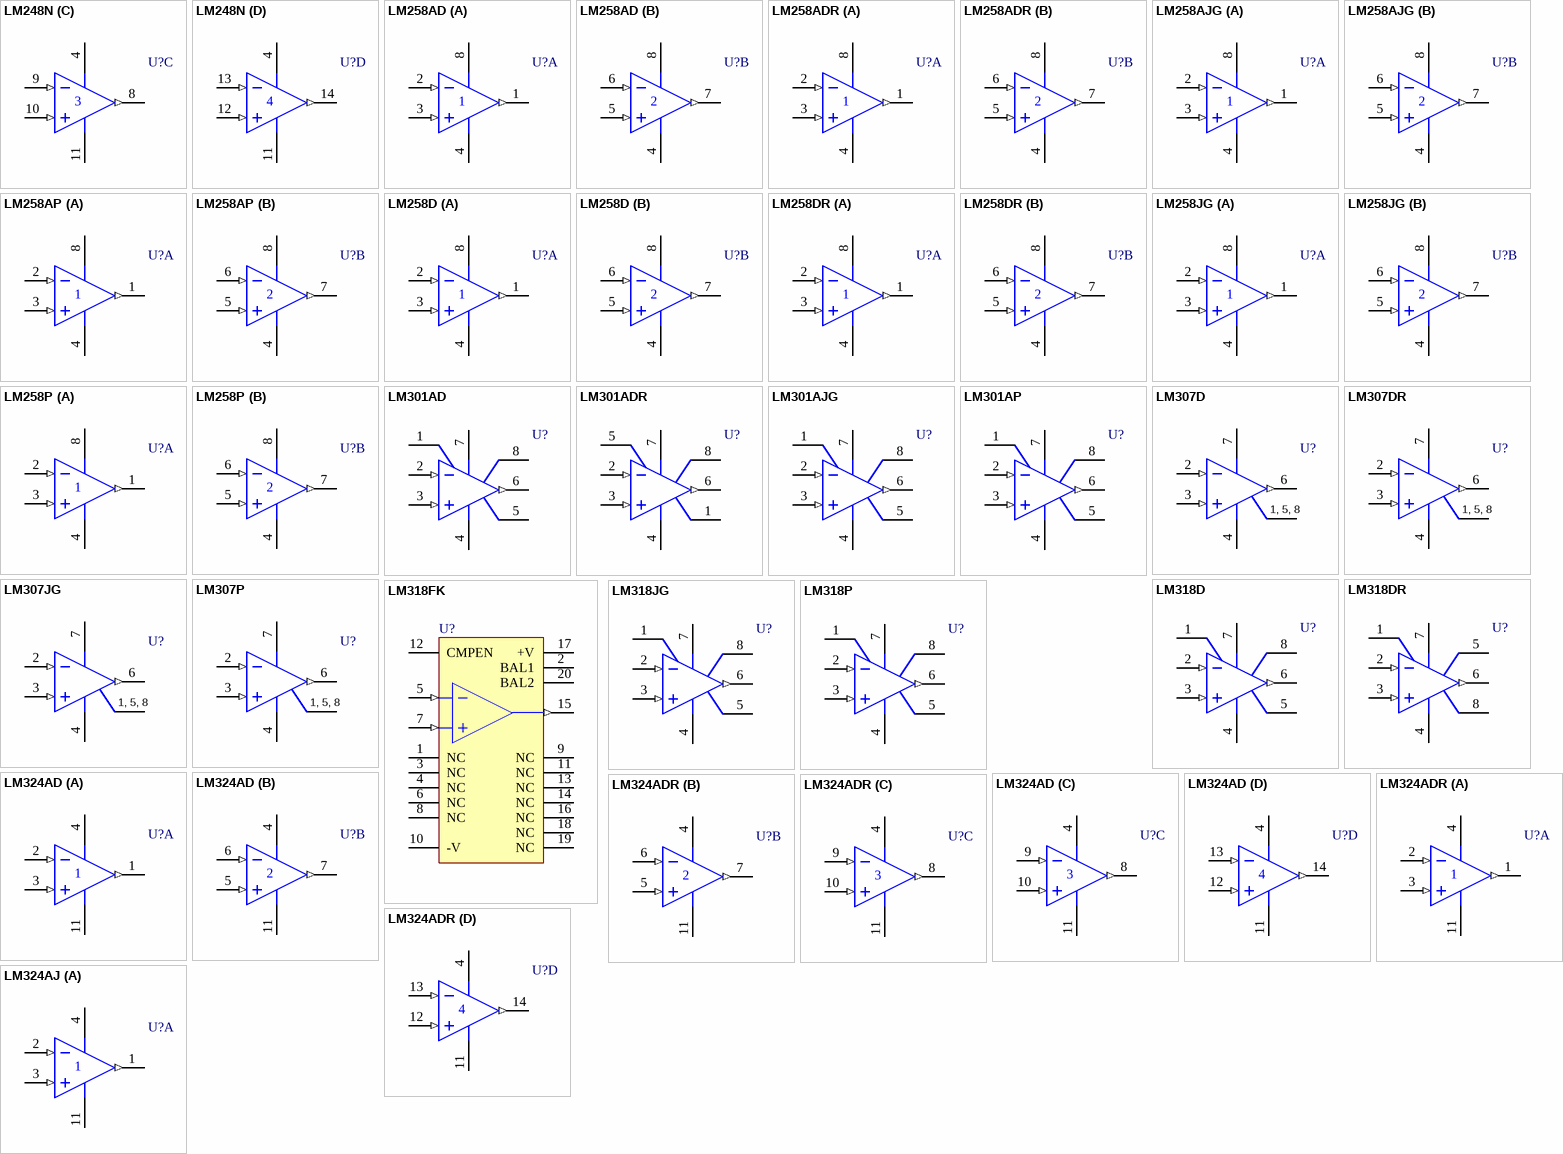
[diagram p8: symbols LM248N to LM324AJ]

## LM248N
designator U?
Quadruple Operational Amplifier
footprint N014 (DIP; 14 Leads; Row Spacing 7.62 mm; Pitch 2.54 mm)
3D model N014 (DIP; 14 Leads; Row Spacing 7.62 mm; Pitch 2.54 mm)
pins on every part: 4 V+ (power), 11 V- (power)
part A pins: 1 OUT (out), 2 IN- (in), 3 IN+ (in)
part B pins: 5 IN+ (in), 6 IN- (in), 7 OUT (out)
part C pins: 8 OUT (out), 9 IN- (in), 10 IN+ (in)
part D pins: 12 IN+ (in), 13 IN- (in), 14 OUT (out)

## LM258AD
designator U?
Dual Operational Amplifier
footprint D008_L (SOIC, 8-Leads, Body 4.9x3.9mm, Pitch 1.27mm, IPC High Density)
footprint D008_M (SOIC, 8-Leads, Body 4.9x3.9mm, Pitch 1.27mm, IPC Low Density)
footprint D008_M (SOIC, 8-Leads, Body 4.9x3.9mm, Pitch 1.27mm, IPC Low Density)
3D model D008 (8-Pin Small Outline Integrated Circuit 1.27 mm Pitch)
pins on every part: 4 V- (power), 8 V+ (power)
part A pins: 1 OUT (out), 2 IN- (in), 3 IN+ (in)
part B pins: 5 IN+ (in), 6 IN- (in), 7 OUT (out)

## LM258ADR
designator U?
Dual Operational Amplifier
footprint D008_L (SOIC, 8-Leads, Body 4.9x3.9mm, Pitch 1.27mm, IPC High Density)
footprint D008_M (SOIC, 8-Leads, Body 4.9x3.9mm, Pitch 1.27mm, IPC Low Density)
footprint D008_M (SOIC, 8-Leads, Body 4.9x3.9mm, Pitch 1.27mm, IPC Low Density)
3D model D008 (8-Pin Small Outline Integrated Circuit 1.27 mm Pitch)
pins on every part: 4 V- (power), 8 V+ (power)
part A pins: 1 OUT (out), 2 IN- (in), 3 IN+ (in)
part B pins: 5 IN+ (in), 6 IN- (in), 7 OUT (out)

## LM258AJG
designator U?
Dual Operational Amplifier
footprint JG008 (DIP; 8 Leads; Row Spacing 7.62 mm; Pitch 2.54 mm)
3D model JG008 (DIP; 8 Leads; Row Spacing 7.62 mm; Pitch 2.54 mm)
pins on every part: 4 V- (power), 8 V+ (power)
part A pins: 1 OUT (out), 2 IN- (in), 3 IN+ (in)
part B pins: 5 IN+ (in), 6 IN- (in), 7 OUT (out)

## LM258AP
designator U?
Dual Operational Amplifier
footprint P008 (DIP; 8 Leads; Row Spacing 7.62 mm; Pitch 2.54 mm)
3D model P008 (DIP; 8 Leads; Row Spacing 7.62 mm; Pitch 2.54 mm)
pins on every part: 4 V- (power), 8 V+ (power)
part A pins: 1 OUT (out), 2 IN- (in), 3 IN+ (in)
part B pins: 5 IN+ (in), 6 IN- (in), 7 OUT (out)

## LM258D
designator U?
Dual Operational Amplifier
footprint D008_L (SOIC, 8-Leads, Body 4.9x3.9mm, Pitch 1.27mm, IPC High Density)
footprint D008_M (SOIC, 8-Leads, Body 4.9x3.9mm, Pitch 1.27mm, IPC Low Density)
footprint D008_M (SOIC, 8-Leads, Body 4.9x3.9mm, Pitch 1.27mm, IPC Low Density)
3D model D008 (8-Pin Small Outline Integrated Circuit 1.27 mm Pitch)
pins on every part: 4 V- (power), 8 V+ (power)
part A pins: 1 OUT (out), 2 IN- (in), 3 IN+ (in)
part B pins: 5 IN+ (in), 6 IN- (in), 7 OUT (out)

## LM258DR
designator U?
Dual Operational Amplifier
footprint D008_L (SOIC, 8-Leads, Body 4.9x3.9mm, Pitch 1.27mm, IPC High Density)
footprint D008_M (SOIC, 8-Leads, Body 4.9x3.9mm, Pitch 1.27mm, IPC Low Density)
footprint D008_M (SOIC, 8-Leads, Body 4.9x3.9mm, Pitch 1.27mm, IPC Low Density)
3D model D008 (8-Pin Small Outline Integrated Circuit 1.27 mm Pitch)
pins on every part: 4 V- (power), 8 V+ (power)
part A pins: 1 OUT (out), 2 IN- (in), 3 IN+ (in)
part B pins: 5 IN+ (in), 6 IN- (in), 7 OUT (out)

## LM258JG
designator U?
Dual Operational Amplifier
footprint JG008 (DIP; 8 Leads; Row Spacing 7.62 mm; Pitch 2.54 mm)
3D model JG008 (DIP; 8 Leads; Row Spacing 7.62 mm; Pitch 2.54 mm)
pins on every part: 4 V- (power), 8 V+ (power)
part A pins: 1 OUT (out), 2 IN- (in), 3 IN+ (in)
part B pins: 5 IN+ (in), 6 IN- (in), 7 OUT (out)

## LM258P
designator U?
Dual Operational Amplifier
footprint P008 (DIP; 8 Leads; Row Spacing 7.62 mm; Pitch 2.54 mm)
3D model P008 (DIP; 8 Leads; Row Spacing 7.62 mm; Pitch 2.54 mm)
pins on every part: 4 V- (power), 8 V+ (power)
part A pins: 1 OUT (out), 2 IN- (in), 3 IN+ (in)
part B pins: 5 IN+ (in), 6 IN- (in), 7 OUT (out)

## LM301AD
designator U?
High Performance Operational Amplifier
footprint D008_L (SOIC, 8-Leads, Body 4.9x3.9mm, Pitch 1.27mm, IPC High Density)
footprint D008_M (SOIC, 8-Leads, Body 4.9x3.9mm, Pitch 1.27mm, IPC Low Density)
footprint D008_M (SOIC, 8-Leads, Body 4.9x3.9mm, Pitch 1.27mm, IPC Low Density)
3D model D008 (8-Pin Small Outline Integrated Circuit 1.27 mm Pitch)
simulation model LM301A (SUBCKT)
pins: 1 BAL1/CMPEN, 2 IN- (in), 3 IN+ (in), 4 V- (power), 5 BAL2, 6 OUT (out), 7 V+ (power), 8 CMPEN

## LM301ADR
designator U?
High-Performance Operational Amplifier; ComponentAvailability: Obsolete
footprint D008_L (SOIC, 8-Leads, Body 4.9x3.9mm, Pitch 1.27mm, IPC High Density)
footprint D008_M (SOIC, 8-Leads, Body 4.9x3.9mm, Pitch 1.27mm, IPC Low Density)
footprint D008_M (SOIC, 8-Leads, Body 4.9x3.9mm, Pitch 1.27mm, IPC Low Density)
3D model D008 (8-Pin Small Outline Integrated Circuit 1.27 mm Pitch)
pins: 1 N1/CMPEN, 2 IN- (in), 3 IN+ (in), 4 V- (power), 5 OS N2, 6 OUT (out), 7 V+ (power), 8 CMPEN

## LM301AJG
designator U?
High Performance Operational Amplifier
footprint JG008 (DIP; 8 Leads; Row Spacing 7.62 mm; Pitch 2.54 mm)
3D model JG008 (DIP; 8 Leads; Row Spacing 7.62 mm; Pitch 2.54 mm)
simulation model LM301A (SUBCKT)
pins: 1 BAL1/CMPEN, 2 IN- (in), 3 IN+ (in), 4 V- (power), 5 BAL2, 6 OUT (out), 7 V+ (power), 8 CMPEN

## LM301AP
designator U?
High Performance Operational Amplifier
footprint P008 (DIP; 8 Leads; Row Spacing 7.62 mm; Pitch 2.54 mm)
3D model P008 (DIP; 8 Leads; Row Spacing 7.62 mm; Pitch 2.54 mm)
simulation model LM301A (SUBCKT)
pins: 1 BAL1/CMPEN, 2 IN- (in), 3 IN+ (in), 4 V- (power), 5 BAL2, 6 OUT (out), 7 V+ (power), 8 CMPEN

## LM307D
designator U?
High-Performance Operational Amplifier
footprint D008_L (SOIC, 8-Leads, Body 4.9x3.9mm, Pitch 1.27mm, IPC High Density)
footprint D008_M (SOIC, 8-Leads, Body 4.9x3.9mm, Pitch 1.27mm, IPC Low Density)
footprint D008_M (SOIC, 8-Leads, Body 4.9x3.9mm, Pitch 1.27mm, IPC Low Density)
3D model D008 (8-Pin Small Outline Integrated Circuit 1.27 mm Pitch)
pins: 1 NC, 2 IN- (in), 3 IN+ (in), 4 V- (power), 5 NC, 6 OUT (out), 7 V+ (power), 8 NC

## LM307DR
designator U?
High-Performance Operational Amplifier
footprint D008_L (SOIC, 8-Leads, Body 4.9x3.9mm, Pitch 1.27mm, IPC High Density)
footprint D008_M (SOIC, 8-Leads, Body 4.9x3.9mm, Pitch 1.27mm, IPC Low Density)
footprint D008_M (SOIC, 8-Leads, Body 4.9x3.9mm, Pitch 1.27mm, IPC Low Density)
3D model D008 (8-Pin Small Outline Integrated Circuit 1.27 mm Pitch)
pins: 1 NC, 2 IN- (in), 3 IN+ (in), 4 V- (power), 5 NC, 6 OUT (out), 7 V+ (power), 8 NC

## LM307JG
designator U?
High-Performance Operational Amplifier
footprint JG008 (DIP; 8 Leads; Row Spacing 7.62 mm; Pitch 2.54 mm)
3D model JG008 (DIP; 8 Leads; Row Spacing 7.62 mm; Pitch 2.54 mm)
pins: 1 NC, 2 IN- (in), 3 IN+ (in), 4 V- (power), 5 NC, 6 OUT (out), 7 V+ (power), 8 NC

## LM307P
designator U?
High-Performance Operational Amplifier; ComponentAvailability: Obsolete
footprint P008 (DIP; 8 Leads; Row Spacing 7.62 mm; Pitch 2.54 mm)
3D model P008 (DIP; 8 Leads; Row Spacing 7.62 mm; Pitch 2.54 mm)
pins: 1 NC, 2 IN- (in), 3 IN+ (in), 4 V- (power), 5 NC, 6 OUT (out), 7 V+ (power), 8 NC

## LM318D
designator U?
Fast General Purpose Operational Amplifier
footprint D008_L (SOIC, 8-Leads, Body 4.9x3.9mm, Pitch 1.27mm, IPC High Density)
footprint D008_M (SOIC, 8-Leads, Body 4.9x3.9mm, Pitch 1.27mm, IPC Low Density)
footprint D008_M (SOIC, 8-Leads, Body 4.9x3.9mm, Pitch 1.27mm, IPC Low Density)
3D model D008 (8-Pin Small Outline Integrated Circuit 1.27 mm Pitch)
simulation model LM318 (SUBCKT)
pins: 1 CMPEN1, 2 IN- (in), 3 IN+ (in), 4 V- (power), 5 CMPEN3, 6 OUT (out), 7 V+ (power), 8 CMPEN2

## LM318DR
designator U?
High-Performance Operational Amplifier
footprint D008_L (SOIC, 8-Leads, Body 4.9x3.9mm, Pitch 1.27mm, IPC High Density)
footprint D008_M (SOIC, 8-Leads, Body 4.9x3.9mm, Pitch 1.27mm, IPC Low Density)
footprint D008_M (SOIC, 8-Leads, Body 4.9x3.9mm, Pitch 1.27mm, IPC Low Density)
3D model D008 (8-Pin Small Outline Integrated Circuit 1.27 mm Pitch)
pins: 1 BAL/COMP, 2 IN- (in), 3 IN+ (in), 4 V- (power), 5 BAL/COMP3, 6 OUT (out), 7 V+ (power), 8 COMP2

## LM318FK
designator U?
Fast General Purpose Operational Amplifier; Note: Pins 1,3,4,6,8,9,11,13,14,16,18 and 19 are not connected
footprint FK020 (Leadless Chip Carrier; 20 Terminals; Body 8.9 x 8.9 mm)
simulation model LM318 (SUBCKT)
pins: 1 NC, 2 BAL1, 3 NC, 4 NC, 5 IN- (in), 6 NC, 7 IN+ (in), 8 NC, 9 NC, 10 -V (power), 11 NC, 12 CMPEN, 13 NC, 14 NC, 15 OUT (out), 16 NC, 17 +V (power), 18 NC, 19 NC, 20 BAL2

## LM318JG
designator U?
Fast General Purpose Operational Amplifier
footprint JG008 (DIP; 8 Leads; Row Spacing 7.62 mm; Pitch 2.54 mm)
3D model JG008 (DIP; 8 Leads; Row Spacing 7.62 mm; Pitch 2.54 mm)
simulation model LM318 (SUBCKT)
pins: 1 CMPEN1, 2 IN- (in), 3 IN+ (in), 4 V- (power), 5 CMPEN3, 6 OUT (out), 7 V+ (power), 8 CMPEN2

## LM318P
designator U?
Fast General Purpose Operational Amplifier
footprint P008 (DIP; 8 Leads; Row Spacing 7.62 mm; Pitch 2.54 mm)
3D model P008 (DIP; 8 Leads; Row Spacing 7.62 mm; Pitch 2.54 mm)
simulation model LM318 (SUBCKT)
pins: 1 CMPEN1, 2 IN- (in), 3 IN+ (in), 4 V- (power), 5 CMPEN3, 6 OUT (out), 7 V+ (power), 8 CMPEN2

## LM324AD
designator U?
Quadruple Operational Amplifier
footprint D014_N (SOIC, 14-Leads, Body 8.7x3.9mm, Pitch 1.27mm, IPC Medium Density)
footprint D014_L (SOIC, 14-Leads, Body 8.7x3.9mm, Pitch 1.27mm, IPC High Density)
footprint D014_M (SOIC, 14-Leads, Body 8.7x3.9mm, Pitch 1.27mm, IPC Low Density)
3D model D014 (14-Pin Small Outline Integrated Circuit 1.27 mm Pitch)
pins on every part: 4 V+ (power), 11 V- (power)
part A pins: 1 OUT (out), 2 IN- (in), 3 IN+ (in)
part B pins: 5 IN+ (in), 6 IN- (in), 7 OUT (out)
part C pins: 8 OUT (out), 9 IN- (in), 10 IN+ (in)
part D pins: 12 IN+ (in), 13 IN- (in), 14 OUT (out)

## LM324ADR
designator U?
Quadruple Operational Amplifier
footprint D014_N (SOIC, 14-Leads, Body 8.7x3.9mm, Pitch 1.27mm, IPC Medium Density)
footprint D014_L (SOIC, 14-Leads, Body 8.7x3.9mm, Pitch 1.27mm, IPC High Density)
footprint D014_M (SOIC, 14-Leads, Body 8.7x3.9mm, Pitch 1.27mm, IPC Low Density)
3D model D014 (14-Pin Small Outline Integrated Circuit 1.27 mm Pitch)
pins on every part: 4 V+ (power), 11 V- (power)
part A pins: 1 OUT (out), 2 IN- (in), 3 IN+ (in)
part B pins: 5 IN+ (in), 6 IN- (in), 7 OUT (out)
part C pins: 8 OUT (out), 9 IN- (in), 10 IN+ (in)
part D pins: 12 IN+ (in), 13 IN- (in), 14 OUT (out)

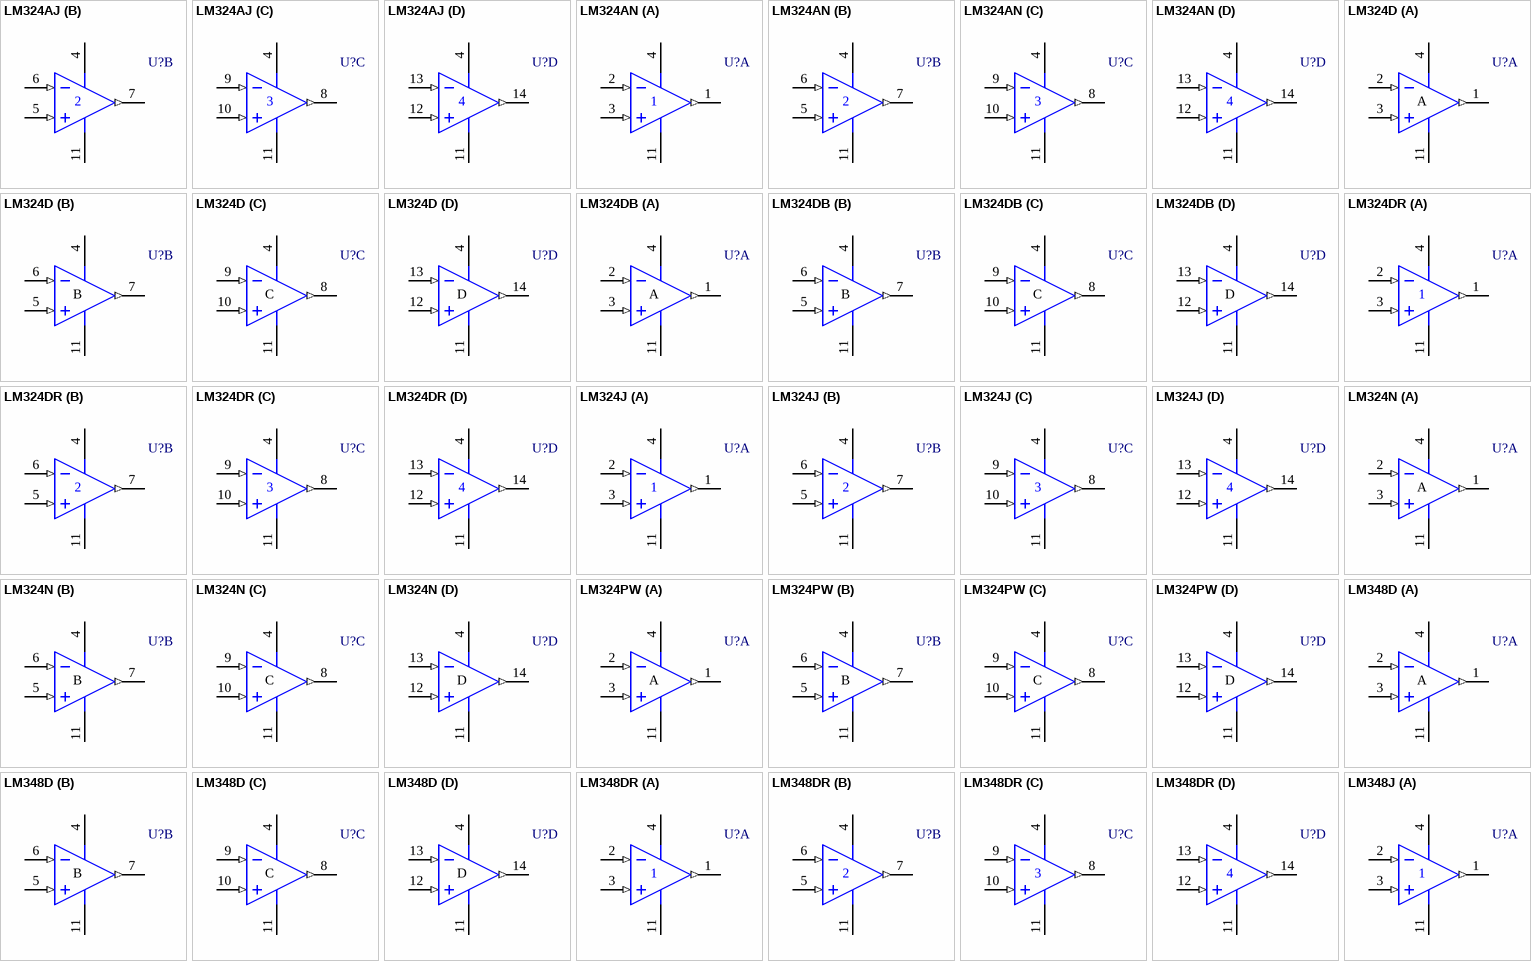
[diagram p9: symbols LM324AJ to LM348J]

## LM324AJ
designator U?
Quadruple Operational Amplifier
footprint J014 (DIP; 14 Leads; Row Spacing 7.62 mm; Pitch 2.54 mm)
3D model J014 (DIP; 14 Leads; Row Spacing 7.62 mm; Pitch 2.54 mm)
pins on every part: 4 V+ (power), 11 V- (power)
part A pins: 1 OUT (out), 2 IN- (in), 3 IN+ (in)
part B pins: 5 IN+ (in), 6 IN- (in), 7 OUT (out)
part C pins: 8 OUT (out), 9 IN- (in), 10 IN+ (in)
part D pins: 12 IN+ (in), 13 IN- (in), 14 OUT (out)

## LM324AN
designator U?
Quadruple Operational Amplifier
footprint N014 (DIP; 14 Leads; Row Spacing 7.62 mm; Pitch 2.54 mm)
3D model N014 (DIP; 14 Leads; Row Spacing 7.62 mm; Pitch 2.54 mm)
pins on every part: 4 V+ (power), 11 V- (power)
part A pins: 1 OUT (out), 2 IN- (in), 3 IN+ (in)
part B pins: 5 IN+ (in), 6 IN- (in), 7 OUT (out)
part C pins: 8 OUT (out), 9 IN- (in), 10 IN+ (in)
part D pins: 12 IN+ (in), 13 IN- (in), 14 OUT (out)

## LM324D
designator U?
Quadruple Operational Amplifier
footprint D014_N (SOIC, 14-Leads, Body 8.7x3.9mm, Pitch 1.27mm, IPC Medium Density)
footprint D014_L (SOIC, 14-Leads, Body 8.7x3.9mm, Pitch 1.27mm, IPC High Density)
footprint D014_M (SOIC, 14-Leads, Body 8.7x3.9mm, Pitch 1.27mm, IPC Low Density)
3D model D014 (14-Pin Small Outline Integrated Circuit 1.27 mm Pitch)
simulation model LM324 (SUBCKT)
pins on every part: 4 V+ (power), 11 V- (power)
part A pins: 1 OUT (out), 2 IN- (in), 3 IN+ (in)
part B pins: 5 IN+ (in), 6 IN- (in), 7 OUT (out)
part C pins: 8 OUT (out), 9 IN- (in), 10 IN+ (in)
part D pins: 12 IN+ (in), 13 IN- (in), 14 OUT (out)

## LM324DB
designator U?
Quadruple Operational Amplifier
footprint DB014_N (SOP, 14-Leads, Body 6.2x5.3mm, Pitch 0.65mm, IPC Medium Density)
footprint DB014_L (SOP, 14-Leads, Body 6.2x5.3mm, Pitch 0.65mm, IPC High Density)
footprint DB014_M (SOP, 14-Leads, Body 6.2x5.3mm, Pitch 0.65mm, IPC Low Density)
3D model DB014 (14-Pin Plastic Small Outline Package 0.65 mm Pitch)
simulation model LM324 (SUBCKT)
pins on every part: 4 V+ (power), 11 V- (power)
part A pins: 1 OUT (out), 2 IN- (in), 3 IN+ (in)
part B pins: 5 IN+ (in), 6 IN- (in), 7 OUT (out)
part C pins: 8 OUT (out), 9 IN- (in), 10 IN+ (in)
part D pins: 12 IN+ (in), 13 IN- (in), 14 OUT (out)

## LM324DR
designator U?
Quadruple Operational Amplifier
footprint D014_N (SOIC, 14-Leads, Body 8.7x3.9mm, Pitch 1.27mm, IPC Medium Density)
footprint D014_L (SOIC, 14-Leads, Body 8.7x3.9mm, Pitch 1.27mm, IPC High Density)
footprint D014_M (SOIC, 14-Leads, Body 8.7x3.9mm, Pitch 1.27mm, IPC Low Density)
3D model D014 (14-Pin Small Outline Integrated Circuit 1.27 mm Pitch)
pins on every part: 4 V+ (power), 11 V- (power)
part A pins: 1 OUT (out), 2 IN- (in), 3 IN+ (in)
part B pins: 5 IN+ (in), 6 IN- (in), 7 OUT (out)
part C pins: 8 OUT (out), 9 IN- (in), 10 IN+ (in)
part D pins: 12 IN+ (in), 13 IN- (in), 14 OUT (out)

## LM324J
designator U?
Quadruple Operational Amplifier
footprint J014 (DIP; 14 Leads; Row Spacing 7.62 mm; Pitch 2.54 mm)
3D model J014 (DIP; 14 Leads; Row Spacing 7.62 mm; Pitch 2.54 mm)
pins on every part: 4 V+ (power), 11 V- (power)
part A pins: 1 OUT (out), 2 IN- (in), 3 IN+ (in)
part B pins: 5 IN+ (in), 6 IN- (in), 7 OUT (out)
part C pins: 8 OUT (out), 9 IN- (in), 10 IN+ (in)
part D pins: 12 IN+ (in), 13 IN- (in), 14 OUT (out)

## LM324N
designator U?
Quadruple Operational Amplifier
footprint N014 (DIP; 14 Leads; Row Spacing 7.62 mm; Pitch 2.54 mm)
3D model N014 (DIP; 14 Leads; Row Spacing 7.62 mm; Pitch 2.54 mm)
simulation model LM324 (SUBCKT)
pins on every part: 4 V+ (power), 11 V- (power)
part A pins: 1 OUT (out), 2 IN- (in), 3 IN+ (in)
part B pins: 5 IN+ (in), 6 IN- (in), 7 OUT (out)
part C pins: 8 OUT (out), 9 IN- (in), 10 IN+ (in)
part D pins: 12 IN+ (in), 13 IN- (in), 14 OUT (out)

## LM324PW
designator U?
Quadruple Operational Amplifier
footprint PW014_N (TSOP, 14-Leads, Body 5x4.4mm, Pitch 0.65mm, IPC Medium Density)
footprint PW014_L (TSOP, 14-Leads, Body 5x4.4mm, Pitch 0.65mm, IPC High Density)
footprint PW014_M (TSOP, 14-Leads, Body 5x4.4mm, Pitch 0.65mm, IPC Low Density)
3D model PW014 (14-Pin Thin Small Outline Package 0.65 mm Pitch)
simulation model LM324 (SUBCKT)
pins on every part: 4 V+ (power), 11 V- (power)
part A pins: 1 OUT (out), 2 IN- (in), 3 IN+ (in)
part B pins: 5 IN+ (in), 6 IN- (in), 7 OUT (out)
part C pins: 8 OUT (out), 9 IN- (in), 10 IN+ (in)
part D pins: 12 IN+ (in), 13 IN- (in), 14 OUT (out)

## LM348D
designator U?
Quadruple Operational Amplifier
footprint D014_N (SOIC, 14-Leads, Body 8.7x3.9mm, Pitch 1.27mm, IPC Medium Density)
footprint D014_L (SOIC, 14-Leads, Body 8.7x3.9mm, Pitch 1.27mm, IPC High Density)
footprint D014_M (SOIC, 14-Leads, Body 8.7x3.9mm, Pitch 1.27mm, IPC Low Density)
3D model D014 (14-Pin Small Outline Integrated Circuit 1.27 mm Pitch)
simulation model LM348 (SUBCKT)
pins on every part: 4 V+ (power), 11 V- (power)
part A pins: 1 OUT (out), 2 IN- (in), 3 IN+ (in)
part B pins: 5 IN+ (in), 6 IN- (in), 7 OUT (out)
part C pins: 8 OUT (out), 9 IN- (in), 10 IN+ (in)
part D pins: 12 IN+ (in), 13 IN- (in), 14 OUT (out)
